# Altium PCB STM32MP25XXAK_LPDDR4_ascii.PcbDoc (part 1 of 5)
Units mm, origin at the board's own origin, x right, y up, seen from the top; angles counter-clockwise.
Board outline 120 x 79.6 mm, 4 copper layers (Top Layer, Signal Layer 1, Signal Layer 2, Bottom Layer), stack 1.614 mm thick; 190 components, 143 nets, 1208 pads, 757 vias.
Unrouted connection lines stored in the file: 3.
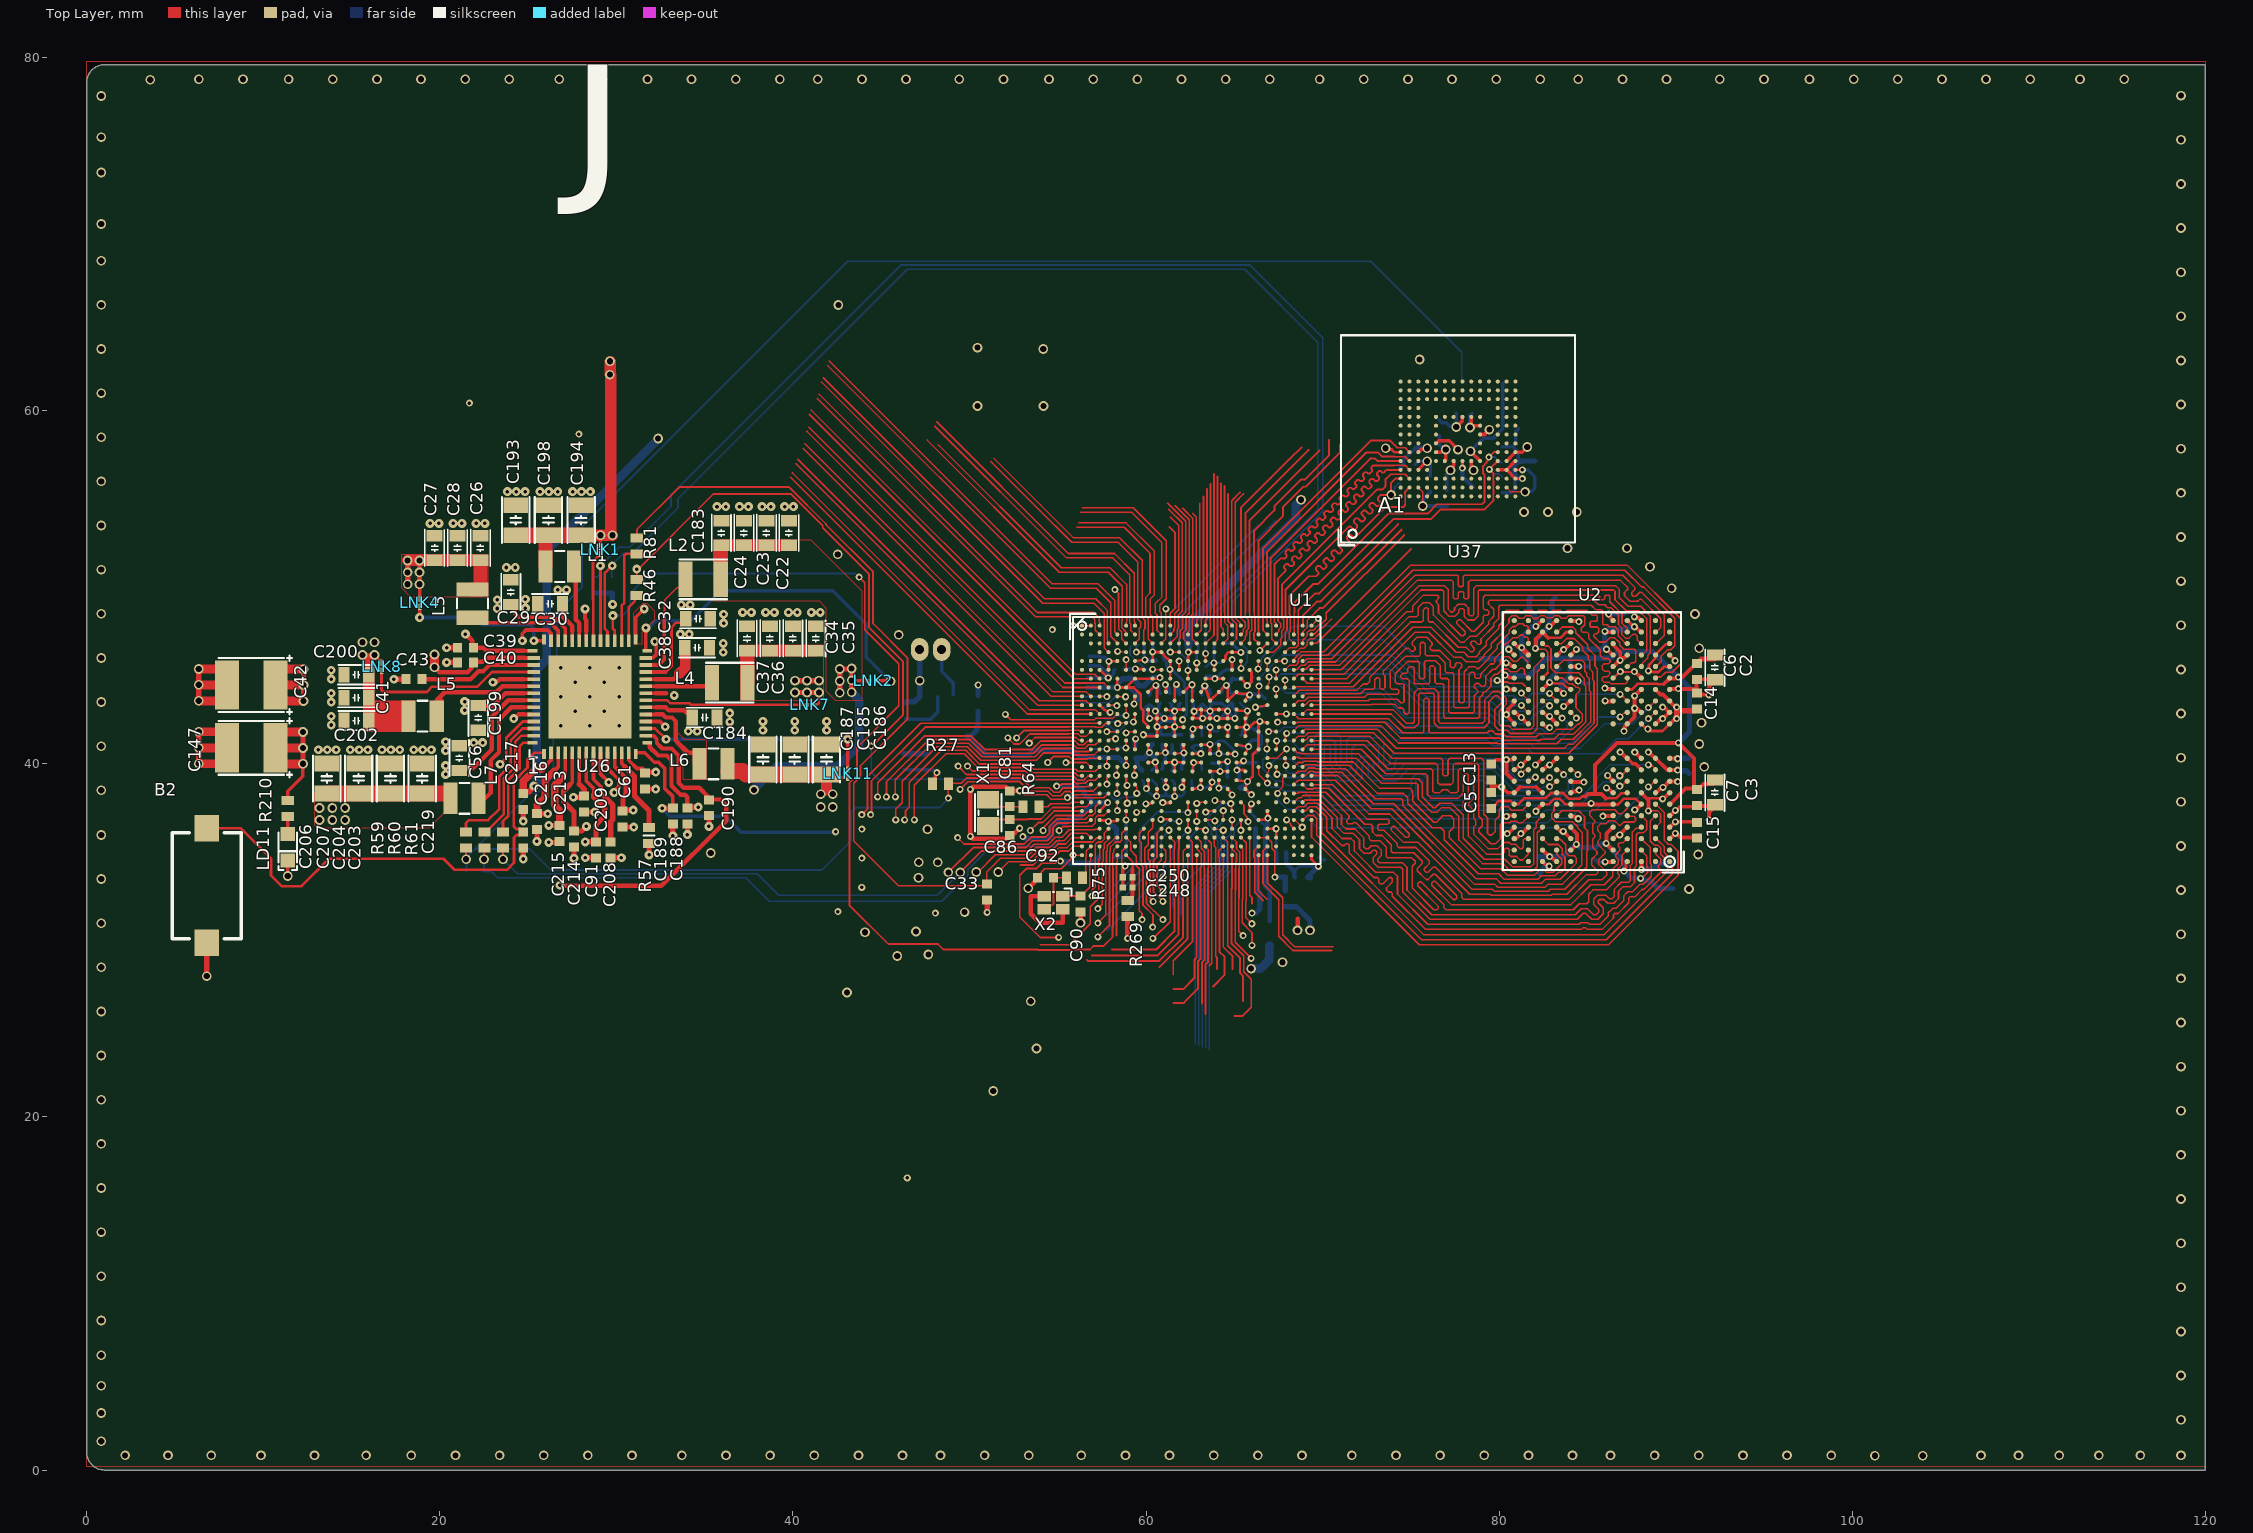
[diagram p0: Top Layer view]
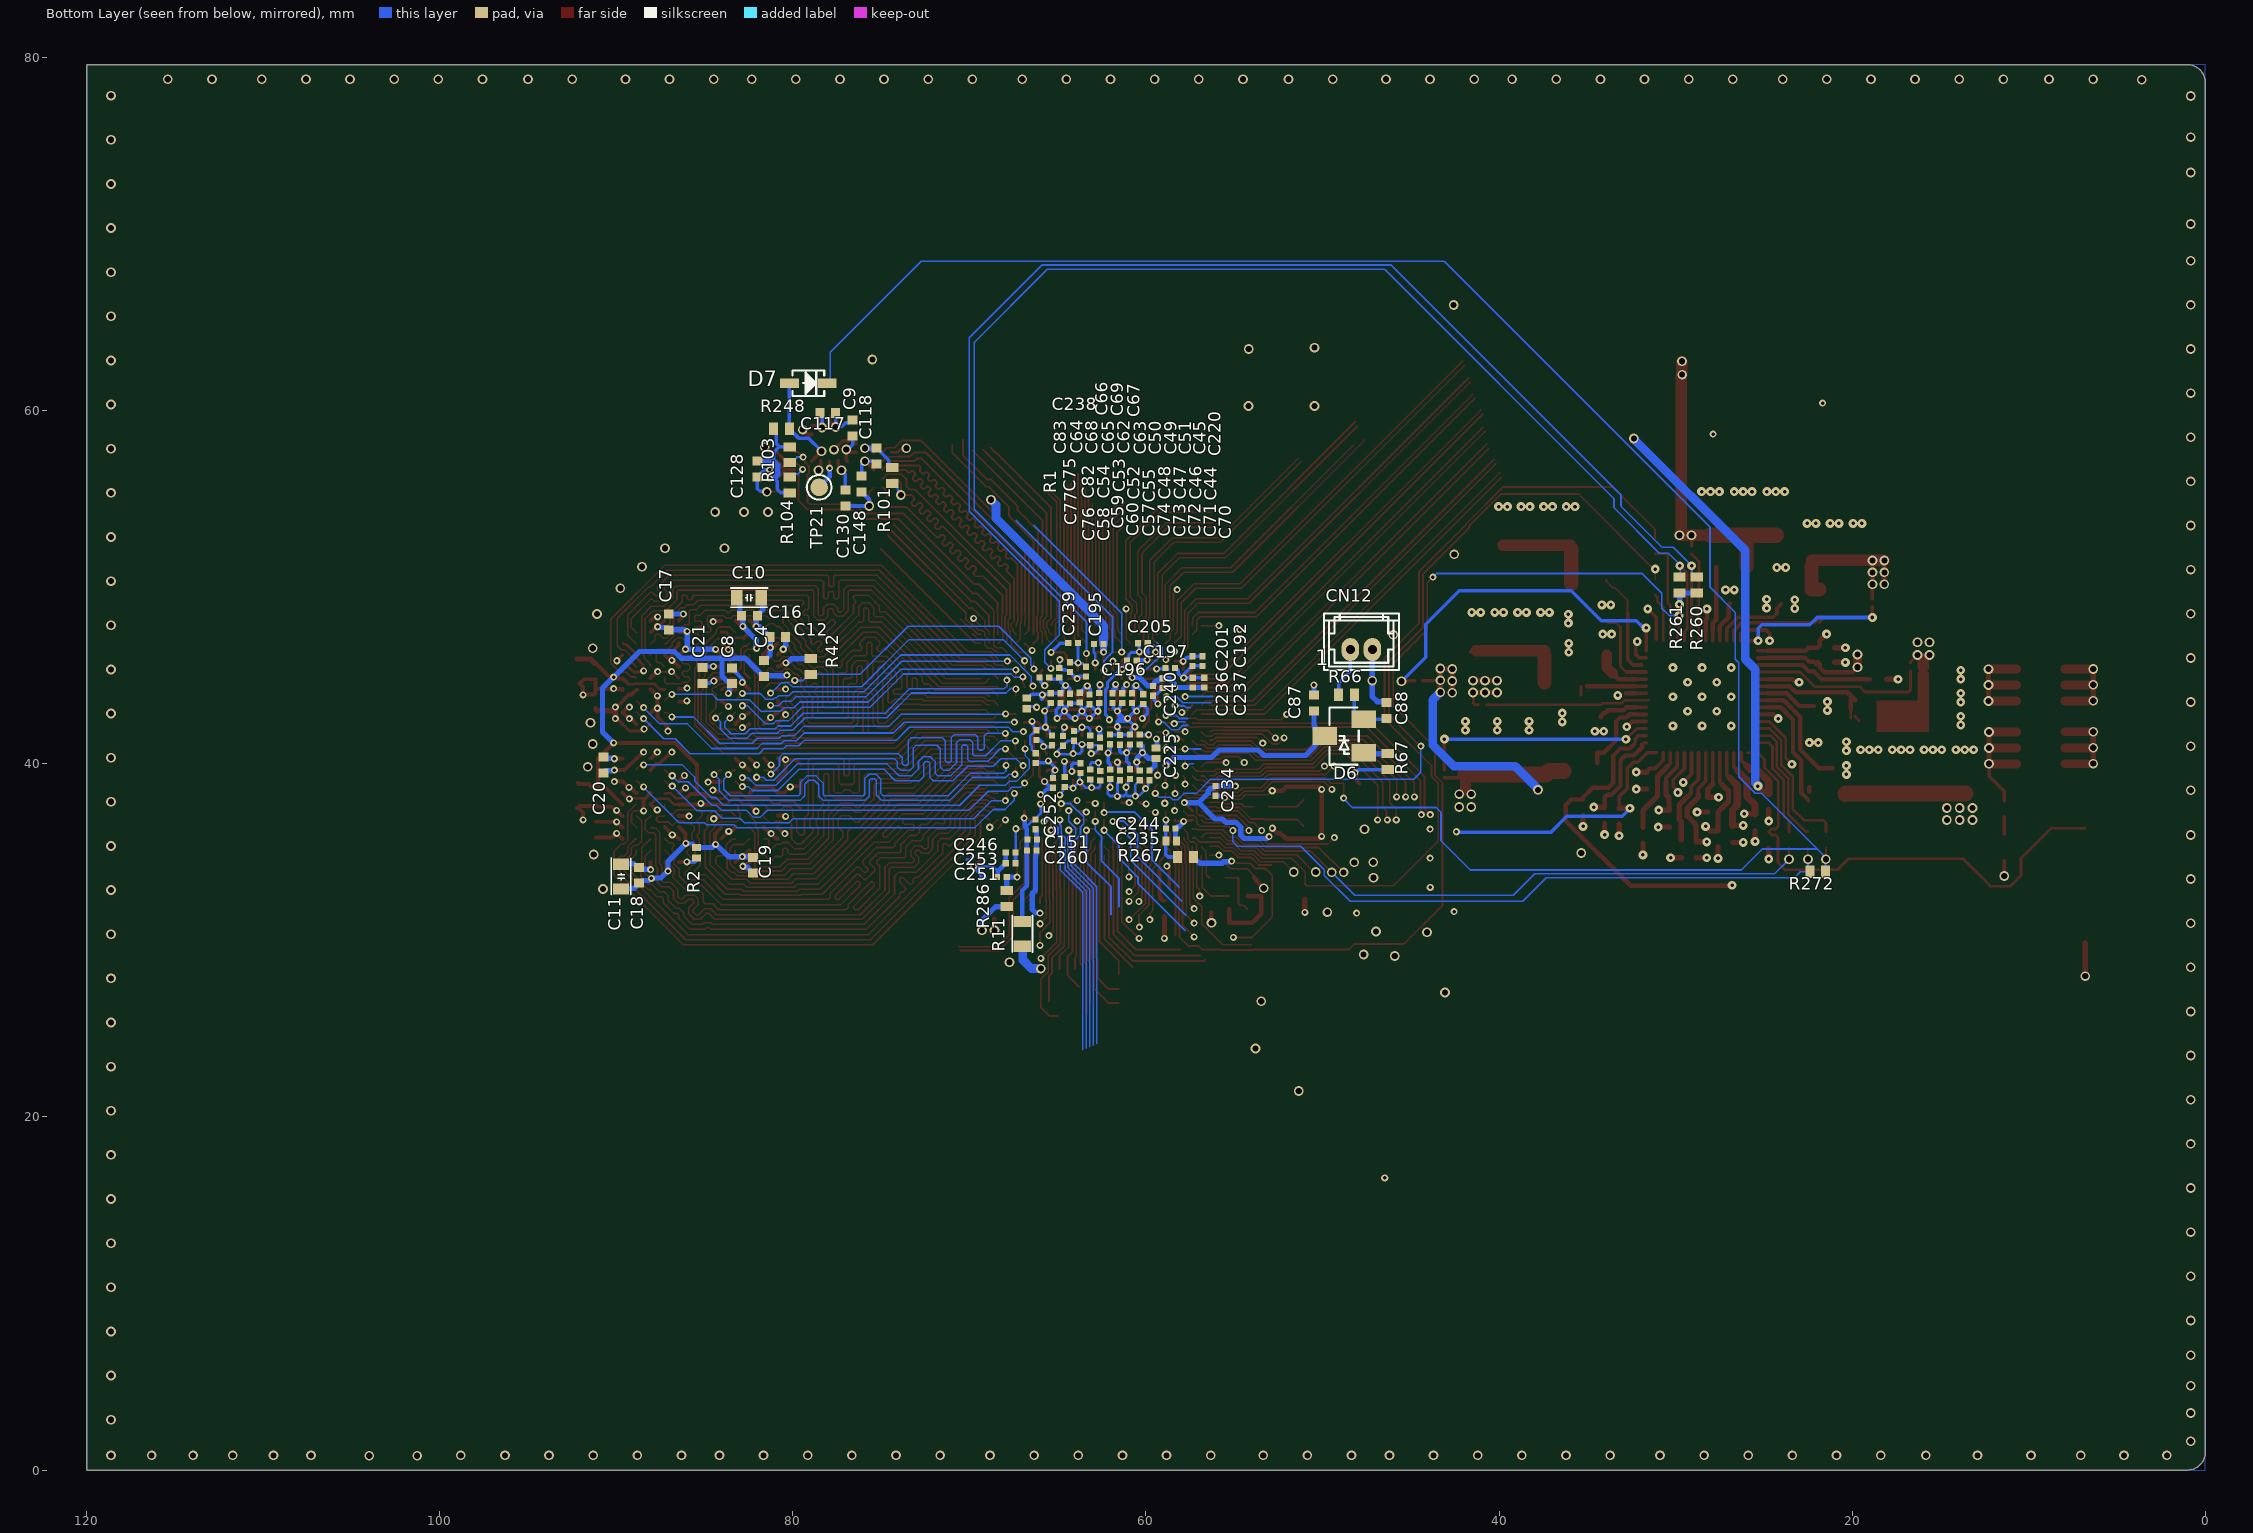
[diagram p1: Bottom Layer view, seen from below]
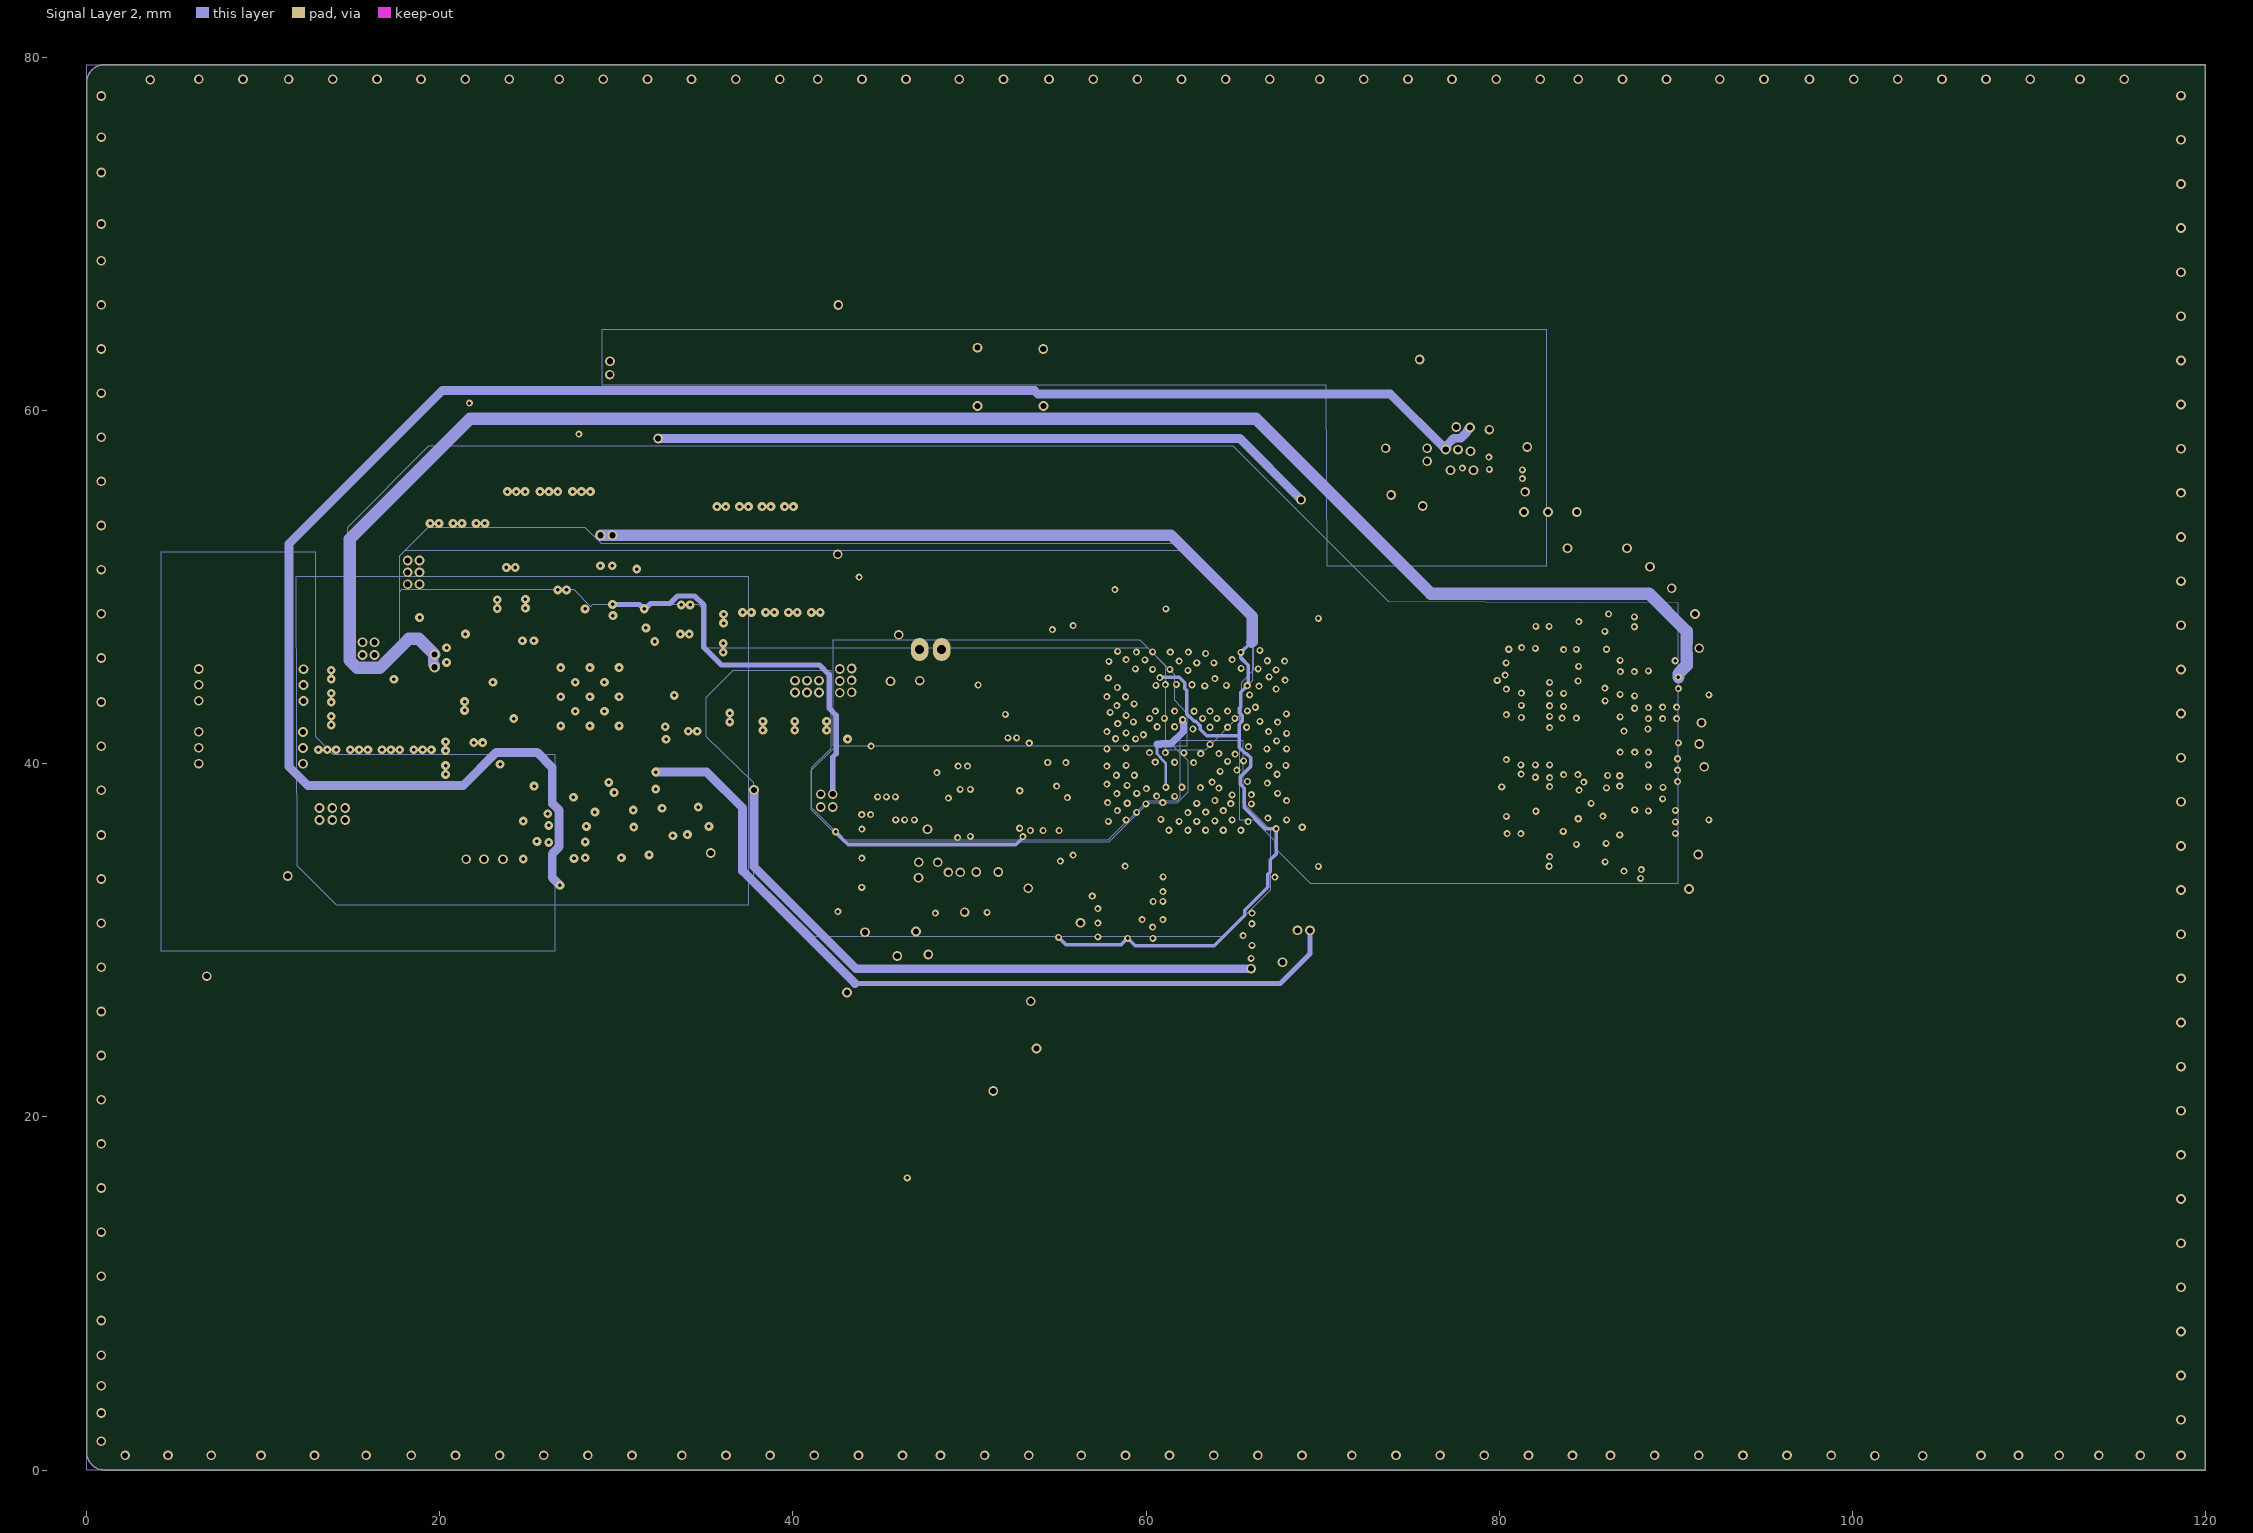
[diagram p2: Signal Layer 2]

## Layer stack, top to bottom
Top Solder: solder mask 0.025, Solder Resist, Dk 3.5
Top Layer: signal copper 0.037
Dielectric 1: prepreg 0.07, Dk 3.8
Signal Layer 1: signal copper 0.035
Dielectric 2: core 1.33, Dk 4.3
Signal Layer 2: signal copper 0.035
Dielectric 3: prepreg 0.07, Dk 3.8
Bottom Layer: signal copper 0.037
Bottom Solder: solder mask 0.025, Solder Resist, Dk 3.5

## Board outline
0,1 0,78.6 cw(c1,78.6) 1,79.6 120,79.6 120,0 1,0 cw(c1,1)

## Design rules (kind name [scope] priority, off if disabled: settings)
AssemblyTestPointUsage [All] p0: scope1count=1 scope1_0_kind=Board scope1_0_value=Board scope2count=1 scope2_0_kind=Board scope2_0_value=Board commentlength=0
AssemblyTestpoint [All] p0: scope1count=1 scope1_0_kind=Board scope1_0_value=Board scope2count=1 scope2_0_kind=Board scope2_0_value=Board commentlength=0
BoardOutlineClearance [All] p0: scope1count=1 scope1_0_kind=Board scope1_0_value=Board scope2count=1 scope2_0_kind=Board scope2_0_value=Board commentlength=0 gap=0.5
BoardOutlineClearance Silkscreen [All] p0 off: scope1count=1 scope1_0_kind=Board scope1_0_value=Board scope2count=1 scope2_0_kind=Board scope2_0_value=Board commentlength=90 gap=0 // Protel DXP Scope 1 Expression Was: OnLayer('Top Overlay') or OnLayer('Bottom Overlay')
BoardOutlineClearance Silkscreen [OnLayer('Top Overlay') or OnLayer('Bottom Overlay')] p1: gap=0 ignorepadtopadclearanceinfootprint=FALSE
BoardOutlineClearance [All] p2: gap=0.5 ignorepadtopadclearanceinfootprint=FALSE
Clearance Clearance_Default [All] p0: scope1count=1 scope1_0_kind=Board scope1_0_value=Board scope2count=1 scope2_0_kind=Board scope2_0_value=Board commentlength=0 gap=0.1
Clearance Clearance_Default [All] p1: gap=0.1 ignorepadtopadclearanceinfootprint=TRUE except(0: SMDPad-Hole Via-Hole; 0.09: Track-Track Track-SMDPad; 0.2: Arc-Hole Track-Hole THPad-Hole Fill-Hole Poly-Hole Region-Hole Text-Hole)
ComponentClearance [All] p0: scope1count=1 scope1_0_kind=Board scope1_0_value=Board scope2count=1 scope2_0_kind=Board scope2_0_value=Board commentlength=0 gap=0.2 collisioncheckmode=3
ComponentClearance [All] p1: gap=0.2 collisioncheckmode=3 verticalgap=0 showdistances=FALSE
DiffPairsRouting 100H [All] p0 off: scope1count=1 scope1_0_kind=Board scope1_0_value=Board scope2count=1 scope2_0_kind=Board scope2_0_value=Board commentlength=70 // Protel DXP Scope 1 Expression Was: InDifferentialPairClass('100H')
DiffPairsRouting 100H [InDifferentialPairClass('100H')] p1: maxlimit=0.254 minlimit=0.16 mostfreqgap=0.16 toplayer_maxgap=0.16 toplayer_minwidth=0.09 toplayer_maxwidth=0.09 toplayer_prefwidth=0.09 midlayer1_minwidth=0.09 midlayer1_maxwidth=0.381 midlayer1_prefwidth=0.09 midlayer4_minwidth=0.09 midlayer4_maxwidth=0.381 midlayer4_prefwidth=0.09 bottomlayer_maxgap=0.16 bottomlayer_minwidth=0.09 bottomlayer_maxwidth=0.09 bottomlayer_prefwidth=0.09 impedanceprofiledriven=TRUE impedanceprofileid={628B3294-B84C-4222-8D8D-B3EA8745C43E} impedanceprofilevalue=100.000000 maxuncoupledlength=12.7
FabricationTestPointUsage [All] p0: scope1count=1 scope1_0_kind=Board scope1_0_value=Board scope2count=1 scope2_0_kind=Board scope2_0_value=Board commentlength=0 valid=0 allowmultiple=FALSE
FabricationTestpoint [All] p0: scope1count=1 scope1_0_kind=Board scope1_0_value=Board scope2count=1 scope2_0_kind=Board scope2_0_value=Board commentlength=0 side=3 testpointundercomponent=TRUE minsize=1.016 maxsize=2.54 preferedsize=1.524 minholesize=0 maxholesize=1.016 preferedholesize=0.813 testpointgrid=0.025
FanoutControl Fanout_Default [All] p0: scope1count=1 scope1_0_kind=Board scope1_0_value=Board scope2count=1 scope2_0_kind=Board scope2_0_value=Board commentlength=30 // Fanout_Default (Default Rule)
FanoutControl Fanout_Small [All] p0 off: scope1count=1 scope1_0_kind=Board scope1_0_value=Board scope2count=1 scope2_0_kind=Board scope2_0_value=Board commentlength=84 // Protel DXP Scope 1 Expression Was: (CompPinCount < 5)   Fanout_Small (Default Rule)
FanoutControl Fanout_SOIC [All] p0 off: scope1count=1 scope1_0_kind=Board scope1_0_value=Board scope2count=1 scope2_0_kind=Board scope2_0_value=Board commentlength=71 // Protel DXP Scope 1 Expression Was: IsSOIC   Fanout_SOIC (Default Rule)
FanoutControl Fanout_LCC [All] p0 off: scope1count=1 scope1_0_kind=Board scope1_0_value=Board scope2count=1 scope2_0_kind=Board scope2_0_value=Board commentlength=69 // Protel DXP Scope 1 Expression Was: IsLCC   Fanout_LCC (Default Rule)
FanoutControl Fanout_BGA [All] p0 off: scope1count=1 scope1_0_kind=Board scope1_0_value=Board scope2count=1 scope2_0_kind=Board scope2_0_value=Board commentlength=69 // Protel DXP Scope 1 Expression Was: IsBGA   Fanout_BGA (Default Rule)
FanoutControl Fanout_BGA [IsBGA] p1: bgadir=Out bgaviamode=Closest fanoutstyle=Auto fanoutdirection=Alternating viagrid=0.025 // Fanout_BGA (Default Rule)
FanoutControl Fanout_LCC [IsLCC] p2: bgadir=Out bgaviamode=Closest fanoutstyle=Auto fanoutdirection=Alternating viagrid=0.025 // Fanout_LCC (Default Rule)
FanoutControl Fanout_SOIC [IsSOIC] p3: bgadir=Out bgaviamode=Closest fanoutstyle=Auto fanoutdirection=Alternating viagrid=0.025 // Fanout_SOIC (Default Rule)
FanoutControl Fanout_Small [(CompPinCount < 5)] p4: bgadir=Out bgaviamode=Closest fanoutstyle=Auto fanoutdirection=OutThenIn viagrid=0.025 // Fanout_Small (Default Rule)
FanoutControl Fanout_Default [All] p5: bgadir=Out bgaviamode=Closest fanoutstyle=Auto fanoutdirection=Alternating viagrid=0.025 // Fanout_Default (Default Rule)
Height [All] p0: scope1count=1 scope1_0_kind=Board scope1_0_value=Board scope2count=1 scope2_0_kind=Board scope2_0_value=Board commentlength=0
HoleSize [All] p0: scope1count=1 scope1_0_kind=Board scope1_0_value=Board scope2count=1 scope2_0_kind=Board scope2_0_value=Board commentlength=0 absolutevalues=TRUE maxlimit=10 minlimit=0.1 maxpercent=80.000 minpercent=20.000
HoleSize [All] p1: absolutevalues=TRUE maxlimit=10 minlimit=0.1 maxpercent=80.000 minpercent=20.000
HoleToHoleClearance [All] p0: scope1count=1 scope1_0_kind=Board scope1_0_value=Board scope2count=1 scope2_0_kind=Board scope2_0_value=Board commentlength=0
HoleToHoleClearance [All] p1: gap=0.25 allowstackedmicrovias=TRUE
LayerPairs [All] p0: scope1count=1 scope1_0_kind=Board scope1_0_value=Board scope2count=1 scope2_0_kind=Board scope2_0_value=Board commentlength=0 enforce=TRUE
MinimumSolderMaskSliver MinimumSolderMaskSliver_SOLDER_BRIDGE [All] p0: scope1count=1 scope1_0_kind=Board scope1_0_value=Board scope2count=1 scope2_0_kind=Footprint scope2_0_value=SOLDER-BRIDGE_R0603-0R commentlength=0
MinimumSolderMaskSliver [All] p0: scope1count=1 scope1_0_kind=Board scope1_0_value=Board scope2count=1 scope2_0_kind=Board scope2_0_value=Board commentlength=0
MinimumSolderMaskSliver MinimumSolderMaskSliver_SOLDER_BRIDGE [All vs HasFootprint('SOLDER-BRIDGE_R0603-0R')] p1: minsoldermaskwidth=0.07
MinimumSolderMaskSliver [All] p2: minsoldermaskwidth=0.075
NetAntennae [All] p0 off: scope1count=1 scope1_0_kind=Board scope1_0_value=Board scope2count=1 scope2_0_kind=Board scope2_0_value=Board commentlength=0
NetAntennae [All] p1 off: netantennaetolerance=0
PasteMaskExpansion [All] p0: scope1count=1 scope1_0_kind=Board scope1_0_value=Board scope2count=1 scope2_0_kind=Board scope2_0_value=Board commentlength=0 expansion=0
PlaneClearance [All] p0: scope1count=1 scope1_0_kind=Board scope1_0_value=Board scope2count=1 scope2_0_kind=Board scope2_0_value=Board commentlength=0 clearance=0.508
PlaneConnect [All] p0: scope1count=1 scope1_0_kind=Board scope1_0_value=Board scope2count=1 scope2_0_kind=Board scope2_0_value=Board commentlength=0 planeconnectstyle=Direct reliefexpansion=0.508 reliefentries=4 reliefconductorwidth=0.21 reliefairgap=0.21
PlaneConnect [All] p1: planeconnectstyle=Direct reliefexpansion=0.508 reliefentries=4 reliefconductorwidth=0.21 reliefairgap=0.21
PolygonConnect PolygonConnect_Default [All] p0: scope1count=1 scope1_0_kind=Board scope1_0_value=Board scope2count=1 scope2_0_kind=Board scope2_0_value=Board commentlength=0 connectstyle=Direct reliefconductorwidth=0.25 reliefentries=4 polygonreliefangle="90 Angle"
PolygonConnect PolygonConnect_Default [All] p1: connectstyle=Direct reliefconductorwidth=0.25 reliefentries=4 polygonreliefangle="90 Angle" airgapwidth=0.25
RoomDefinition RoomDefinition_eMMC [All] p0 off: scope1count=1 scope1_0_kind=Board scope1_0_value=Board scope2count=1 scope2_0_kind=Board scope2_0_value=Board commentlength=44 region_x1=366825123 region_y1=339606300 region_x2=369695387 region_y2=342521149 confinementstyle=ConfineIn // Protel DXP Scope 1 Expression Was: False
RoomDefinition RoomDefinition_DDR [All] p0 off: scope1count=1 scope1_0_kind=Board scope1_0_value=Board scope2count=1 scope2_0_kind=Board scope2_0_value=Board commentlength=44 region_x1=368782677 region_y1=331242320 region_x2=373417322 region_y2=337462792 confinementstyle=ConfineIn // Protel DXP Scope 1 Expression Was: False
RoomDefinition U_PMIC [All] p0: scope1count=1 scope1_0_kind=ComponentClass scope1_0_value=U_PMIC scope2count=1 scope2_0_kind=Board scope2_0_value=Board commentlength=0 region_x1=359568897 region_y1=331484252 region_x2=365277559 region_y2=337192914 confinementstyle=ConfineIn
RoomDefinition RoomDefinition_eMMC [False] p1: confinementstyle=ConfineIn formatcopy=TRUE lockcomponents=FALSE outline 74.056,62.109 81.346,62.109 81.346,54.705 74.056,54.705
RoomDefinition RoomDefinition_DDR [False] p2: confinementstyle=ConfineIn formatcopy=TRUE lockcomponents=FALSE outline 79.028,49.26 90.8,49.26 90.8,33.46 79.028,33.46
RoomDefinition U_PMIC [InComponentClass('U_PMIC')] p3: confinementstyle=ConfineIn formatcopy=TRUE lockcomponents=FALSE outline 55.625,48.575 70.125,48.575 70.125,34.075 55.625,34.075
RoutingCorners [All] p0: scope1count=1 scope1_0_kind=Board scope1_0_value=Board scope2count=1 scope2_0_kind=Board scope2_0_value=Board commentlength=0 cornerstyle=45-Degree minsetback=2.54 maxsetback=2.54
RoutingLayers [All] p0: scope1count=1 scope1_0_kind=Board scope1_0_value=Board scope2count=1 scope2_0_kind=Board scope2_0_value=Board commentlength=0 top layer=Automatic mid layer 1=Automatic mid layer 4=Automatic bottom layer=Automatic
RoutingPriority [All] p0: scope1count=1 scope1_0_kind=Board scope1_0_value=Board scope2count=1 scope2_0_kind=Board scope2_0_value=Board commentlength=0
RoutingTopology [All] p0: scope1count=1 scope1_0_kind=Board scope1_0_value=Board scope2count=1 scope2_0_kind=Board scope2_0_value=Board commentlength=0 topology=Shortest
RoutingVias RoutingVias_Default [All] p0 off: scope1count=1 scope1_0_kind=Board scope1_0_value=Board scope2count=1 scope2_0_kind=Board scope2_0_value=Board commentlength=83 holewidth=0.15 width=0.4 viastyle="Through Hole" minholewidth=0.15 minwidth=0.4 maxholewidth=0.35 maxwidth=0.6 // Protel DXP Scope 1 Expression Was: InDrillLayerPair('Top Layer - Bottom Layer')
RoutingVias RoutingVias_Default [InDrillLayerPair('Top Layer - Bottom Layer')] p1: holewidth=0.15 width=0.4 viastyle="Through Hole" minholewidth=0.15 minwidth=0.4 maxholewidth=0.35 maxwidth=0.6 useviatemplates=TRUE viatemplateguid#1={8082EAB8-D593-4669-9C8E-234CD125C595} viatemplateguid#2={6F43EA8F-9356-47F3-9E64-8437B01C3073} viatemplateguid#3={0C56A9B8-CF93-463B-97D5-BDCC265789B0} viatemplateguid#4={9F28DA9E-6088-4B56-A5CF-E6C86A3E97F7} viatemplatename#1=v40h20m0mx0 viatemplatename#2=v40h20m25 viatemplatename#3=v50h20m25 viatemplatename#4=v55h35m40mx40
ShortCircuit [All] p0: scope1count=1 scope1_0_kind=Board scope1_0_value=Board scope2count=1 scope2_0_kind=Board scope2_0_value=Board commentlength=0 allowed=FALSE
SilkToBoardRegionClearance [All] p0: scope1count=1 scope1_0_kind=Board scope1_0_value=Board scope2count=1 scope2_0_kind=Board scope2_0_value=Board commentlength=0
SilkToSilkClearance [All] p0: scope1count=1 scope1_0_kind=Board scope1_0_value=Board scope2count=1 scope2_0_kind=Board scope2_0_value=Board commentlength=0
SilkToSilkClearance [All] p1: silktosilkclearance=0.2
SilkToSolderMaskClearance [All] p0 off: scope1count=1 scope1_0_kind=Board scope1_0_value=Board scope2count=1 scope2_0_kind=Board scope2_0_value=Board commentlength=44 // Protel DXP Scope 1 Expression Was: IsPad
SilkToSolderMaskClearance [IsPad] p1: minsilkscreentomaskgap=0.015 clearancetoexposedcopper=TRUE
SolderMaskExpansion [All] p0: scope1count=1 scope1_0_kind=Board scope1_0_value=Board scope2count=1 scope2_0_kind=Board scope2_0_value=Board commentlength=0 expansion=0.1
SolderMaskExpansion [All] p1: expansion=0.1 istentingtop=FALSE
UnRoutedNet [All] p0 off: scope1count=1 scope1_0_kind=Board scope1_0_value=Board scope2count=1 scope2_0_kind=Board scope2_0_value=Board commentlength=0
UnRoutedNet [All] p1 off:
UnpouredPolygon [All] p0: scope1count=1 scope1_0_kind=Board scope1_0_value=Board scope2count=1 scope2_0_kind=Board scope2_0_value=Board commentlength=0
ViasUnderSMD [All] p0: scope1count=1 scope1_0_kind=PadClass scope1_0_value=PC_VIAS-IN-PAD_OK scope2count=1 scope2_0_kind=Board scope2_0_value=Board commentlength=0 allowed=TRUE
ViasUnderSMD [InPadClass('PC_VIAS-IN-PAD_OK')] p1: allowed=TRUE
Width Width_Default [All] p0: scope1count=1 scope1_0_kind=Net scope1_0_value=GND scope2count=1 scope2_0_kind=Board scope2_0_value=Board commentlength=0 maxlimit=10 minlimit=0.09 preferedwidth=0.3
Width Width_SINGLE_DDR_55R [All] p0 off: scope1count=1 scope1_0_kind=NetClass scope1_0_value=55H scope2count=1 scope2_0_kind=Board scope2_0_value=Board commentlength=0 maxlimit=0.199 minlimit=0.078 preferedwidth=0.199
Width Width_SINGLE_50R [All] p0 off: scope1count=1 scope1_0_kind=NetClass scope1_0_value=50H scope2count=1 scope2_0_kind=Board scope2_0_value=Board commentlength=0 maxlimit=0.199 minlimit=0.078 preferedwidth=0.199
Width Width_SINGLE_50R [InNetClass('50H')] p1 off: maxlimit=0.199 minlimit=0.078 preferedwidth=0.199 toplayer_minwidth=0.09 toplayer_maxwidth=0.11 toplayer_prefwidth=0.11 bottomlayer_minwidth=0.11 bottomlayer_maxwidth=0.11 bottomlayer_prefwidth=0.11 impedanceprofiledriven=TRUE impedanceprofileid={152E730A-FDA4-4006-BF82-0EE0D5C1A339} impedanceprofilevalue=50.000000 minimp=50.000000 maximp=50.000000 favimp=50.000000
Width Width_SINGLE_DDR_55R [InNetClass('55H')] p2 off: maxlimit=0.199 minlimit=0.078 preferedwidth=0.199 toplayer_minwidth=0.09 toplayer_maxwidth=0.09 toplayer_prefwidth=0.09 bottomlayer_minwidth=0.09 bottomlayer_maxwidth=0.09 bottomlayer_prefwidth=0.09 impedanceprofiledriven=TRUE impedanceprofileid={D5948A69-504E-4D29-B9E5-77B49DDD78E4} impedanceprofilevalue=55.000000 minimp=50.000000 maximp=50.000000 favimp=50.000000
Width Width_Default [InNet('GND')] p3: maxlimit=10 minlimit=0.09 preferedwidth=0.3 toplayer_prefwidth=0.09 bottomlayer_prefwidth=0.09 minimp=50.000000 maximp=50.000000 favimp=50.000000
15 further rules are at their usual default settings.

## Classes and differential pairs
net class 100H: DDR_CLK_A_N DDR_CLK_A_P DDR_CLK_B_N DDR_CLK_B_P DDR_DQS0_A_N DDR_DQS0_A_P DDR_DQS0_B_N DDR_DQS0_B_P DDR_DQS1_A_N DDR_DQS1_A_P DDR_DQS1_B_N DDR_DQS1_B_P
net class eMMC.SDMMC2_D[0..7]: eMMC.SDMMC2_CK eMMC.SDMMC2_CMD eMMC.SDMMC2_D0 eMMC.SDMMC2_D1 eMMC.SDMMC2_D2 eMMC.SDMMC2_D3 eMMC.SDMMC2_D4 eMMC.SDMMC2_D5 eMMC.SDMMC2_D6 eMMC.SDMMC2_D7
component class U_eMMC: C9 C117 C118 C128 C130 C148 D7 R101 R103 R104 R248 TP21 U37
component class "U_STM32MP25XXAK I_Os": C33 C81 C86 C90 C92 R27 R64 R75 R260 R261 R272 U1 X1 X2
component class "U_STM32MP25XXAK Power": C44 C45 C46 C47 C48 C49 C50 C51 C52 C53 C54 C55 C57 C58 C59 C60 C62 C63 C64 C65 C66 C67 C68 C69 C70 C71 C72 C73 C74 C75 C76 C77 C82 C83 C87 C88 C151 C192 C195 C196 C197 C201 C205 C220 C225 C234 C235 C236 C237 C238 C239 C240 C244 C246 C248 C250 C251 C252 C253 C260 CN12 D6 R11 R66 R67 R267 R269 R286
component class U_PMIC: B2 C22 C23 C24 C26 C27 C28 C29 C30 C32 C34 C35 C36 C37 C38 C39 C40 C41 C42 C43 C56 C61 C91 C147 C183 C184 C185 C186 C187 C188 C189 C190 C193 C194 C198 C199 C200 C202 C203 C204 C206 C207 C208 C209 C213 C214 C215 C216 C217 C219 L1 L2 L3 L4 L5 L6 L7 LD11 LNK1 LNK2 LNK4 LNK7 LNK8 LNK11 R46 R57 R59 R60 R61 R81 R210 U26
differential pair CLKB: +DDR_CLK_B_P -DDR_CLK_B_N
differential pair CLKA: +DDR_CLK_A_P -DDR_CLK_A_N
differential pair DQS1B: +DDR_DQS1_B_P -DDR_DQS1_B_N
differential pair DQS0B: +DDR_DQS0_B_P -DDR_DQS0_B_N
differential pair DQS1A: +DDR_DQS1_A_P -DDR_DQS1_A_N
differential pair " ": +DDR_DQS0_A_P -DDR_DQS0_A_N

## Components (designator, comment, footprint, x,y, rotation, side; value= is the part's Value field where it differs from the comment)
B2 "SW_PUSH_SMD_2P" SWI_WE_434121025816 6.795,33.104 r90 top
C2 "Capacitor" C0603 92.225,45.46 r90 top
C3 "Capacitor" C0603 92.225,38.385 r90 top
C4 "100nF" C0402 81.63,45.397 r90 bottom
C5 "100nF" C0402 79.559,37.929 r90 top
C6 "100nF" C0402 91.209,45.24 r270 top
C7 "100nF" C0402 91.209,38.09 r270 top
C8 "100nF" C0402 83.461,44.99 r90 bottom
C9 "Capacitor" C0402 76.615,59.03 r270 bottom
C10 "Capacitor" C0603 82.486,49.415 r0 bottom
C11 "Capacitor" C0603 89.736,33.615 r270 bottom
C12 "100nF" C0402 80.861,47.18 r0 bottom
C13 "100nF" C0402 79.559,39.529 r270 top
C14 "100nF" C0402 91.209,43.565 r90 top
C15 "100nF" C0402 91.209,36.24 r270 top
C16 "100nF" C0402 82.461,48.39 r180 bottom
C17 "100nF" C0402 87.036,48.04 r90 bottom
C18 "100nF" C0402 88.711,33.69 r90 bottom
C19 "100nF" C0402 82.261,34.255 r270 bottom
C20 "100nF" C0402 90.736,39.94 r270 bottom
C21 "100nF" C0402 85.111,45.015 r90 bottom
C22 "Capacitor" C0603 39.775,53.075 r270 top
C23 "Capacitor" C0603 38.5,53.075 r270 top
C24 "Capacitor" C0603 37.225,53.075 r270 top
C26 "Capacitor" C0603 22.3,52.225 r270 top
C27 "Capacitor" C0603 19.7,52.225 r270 top
C28 "Capacitor" C0603 21,52.225 r270 top
C29 "Capacitor" C0603 24.025,49.725 r270 top
C30 "Capacitor" C0603 26.25,49.075 r0 top
C32 "Capacitor" C0603 34.625,48.225 r180 top
C33 "Capacitor" C0402 51,32.75 r90 top
C34 "Capacitor" C0603 40,47.1 r270 top
C35 "Capacitor" C0603 41.3,47.1 r270 top
C36 "Capacitor" C0603 38.7,47.1 r270 top
C37 "Capacitor" C0603 37.4,47.1 r270 top
C38 "Capacitor" C0603 34.575,46.575 r180 top
C39 "Capacitor" C0402 21.445,46.575 r0 top
C40 "Capacitor" C0402 21.445,45.75 r0 top
C41 "Capacitor" C0603 15.275,43.75 r0 top
C42 "Cap_POL_TANA" CPOL_TCJ-B_1210_H210 9.311,44.468 r180 top
C43 "Capacitor" C0402 18.535,44.8 r0 top
C44 "1uF" C0201_MURATA_GRM033_H0P3 60.351,41.38 r270 bottom
C45 "1uF" C0201_MURATA_GRM033_H0P3 60.16,43.67 r270 bottom
C46 "1uF" C0201_MURATA_GRM033_H0P3 60.915,41.38 r90 bottom
C47 "1uF" C0201_MURATA_GRM033_H0P3 61.476,41.356 r270 bottom
C48 "1uF" C0201_MURATA_GRM033_H0P3 62.038,41.382 r90 bottom
C49 "1uF" C0201_MURATA_GRM033_H0P3 61.35,43.725 r270 bottom
C50 "1uF" C0201_MURATA_GRM033_H0P3 61.9,43.725 r270 bottom
C51 "1uF" C0201_MURATA_GRM033_H0P3 60.8,43.725 r270 bottom
C52 "1uF" C0201_MURATA_GRM033_H0P3 63.162,41.332 r270 bottom
C53 "1uF" C0201_MURATA_GRM033_H0P3 64.083,41.581 r270 bottom
C54 "1uF" C0201_MURATA_GRM033_H0P3 64.706,41.304 r270 bottom
C55 "1uF" C0201_MURATA_GRM033_H0P3 62.6,41.2 r270 bottom
C56 "Capacitor" C0603 21.1,40.325 r270 top
C57 "1uF" C0201_MURATA_GRM033_H0P3 62.592,39.328 r270 bottom
C58 "1uF" C0201_MURATA_GRM033_H0P3 64.607,38.972 r270 bottom
C59 "1uF" C0201_MURATA_GRM033_H0P3 63.714,39.761 r270 bottom
C60 "1uF" C0201_MURATA_GRM033_H0P3 63.154,39.397 r270 bottom
C61 "Capacitor" C0402 31.625,39.02 r90 top
C62 "1uF" C0201_MURATA_GRM033_H0P3 63.2,43.65 r90 bottom
C63 "1uF" C0201_MURATA_GRM033_H0P3 62.65,43.73 r270 bottom
C64 "1uF" C0201_MURATA_GRM033_H0P3 64.85,43.725 r270 bottom
C65 "1uF" C0201_MURATA_GRM033_H0P3 63.75,43.75 r90 bottom
C66 "1uF" C0201_MURATA_GRM033_H0P3 64.915,45.16 r90 bottom
C67 "1uF" C0201_MURATA_GRM033_H0P3 63.4,45.225 r270 bottom
C68 "1uF" C0201_MURATA_GRM033_H0P3 64.3,43.7 r270 bottom
C69 "1uF" C0201_MURATA_GRM033_H0P3 64.305,45.477 r270 bottom
C70 "1uF" C0201_MURATA_GRM033_H0P3 59.805,39.35 r90 bottom
C71 "1uF" C0201_MURATA_GRM033_H0P3 60.355,39.35 r270 bottom
C72 "1uF" C0201_MURATA_GRM033_H0P3 60.905,39.423 r270 bottom
C73 "1uF" C0201_MURATA_GRM033_H0P3 61.467,39.349 r90 bottom
C74 "1uF" C0201_MURATA_GRM033_H0P3 62.03,39.408 r270 bottom
C75 "1uF" C0201_MURATA_GRM033_H0P3 66.205,41.625 r90 bottom
C76 "1uF" C0201_MURATA_GRM033_H0P3 65.274,38.923 r270 bottom
C77 "1uF" C0201_MURATA_GRM033_H0P3 66.25,40.325 r270 bottom
C81 "Capacitor" C0402 52.285,38.025 r90 top
C82 "1uF" C0201_MURATA_GRM033_H0P3 65.325,41.325 r90 bottom
C83 "1uF" C0201_MURATA_GRM033_H0P3 65.395,43.725 r270 bottom
C86 "Capacitor" C0402 52.285,36.4 r270 top
C87 "" C0402 50.485,43.438 r270 bottom
C88 "Capacitor" C0402 46.382,43.015 r270 bottom
C90 "Capacitor" C0402 56.293,32.06 r90 top
C91 "Capacitor" C0402 28.85,35.13 r270 top
C92 "Capacitor" C0402 54.309,33.546 r180 top
C117 "Capacitor" C0402 78.025,59.864 r0 bottom
C118 "Capacitor" C0402 75.26,57.43 r90 bottom
C128 "Capacitor" C0402 82.015,56.705 r90 bottom
C130 "Capacitor" C0402 77.027,55.055 r270 bottom
C147 "Cap_POL_TANA" CPOL_TCJ-B_1210_H210 9.311,40.906 r180 top
C148 "Capacitor" C0402 76.11,55.855 r270 bottom
C151 "Capacitor" C0201_MURATA_GRM033_H0P3 66.446,35.716 r0 bottom
C183 "Capacitor" C0603 35.95,53.075 r270 top
C184 "Capacitor" C0603 34.997,42.625 r180 top
C185 "Capacitor" C0805 40.1,40.25 r270 top
C186 "Capacitor" C0805 41.9,40.25 r270 top
C187 "Capacitor" C0805 38.3,40.25 r270 top
C188 "Capacitor" C0402 34.025,37.04 r90 top
C189 "Capacitor" C0402 33.2,37.04 r90 top
C190 "Capacitor" C0402 35.25,37.515 r270 top
C192 "Capacitor" C0201_MURATA_GRM033_H0P3 56.8,45.825 r90 bottom
C193 "Capacitor" C0805 24.3,53.8 r270 top
C194 "Capacitor" C0805 28,53.8 r270 top
C195 "Capacitor" C0201_MURATA_GRM033_H0P3 62.675,46.787 r180 bottom
C196 "Capacitor" C0201_MURATA_GRM033_H0P3 60.8,45.85 r0 bottom
C197 "Capacitor" C0201_MURATA_GRM033_H0P3 58.625,45.425 r0 bottom
C198 "Capacitor" C0805 26.15,53.8 r270 top
C199 "Capacitor" C0603 22.175,42.6 r90 top
C200 "Capacitor" C0603 15.275,45.05 r0 top
C201 "Capacitor" C0201_MURATA_GRM033_H0P3 57.375,45.825 r90 bottom
C202 "Capacitor" C0603 15.275,42.45 r0 top
C203 "Capacitor" C0805 19,39.173 r270 top
C204 "Capacitor" C0805 17.2,39.173 r270 top
C205 "Capacitor" C0201_MURATA_GRM033_H0P3 60.177,46.829 r0 bottom
C206 "Capacitor" C0805 13.6,39.173 r270 top
C207 "Capacitor" C0805 15.4,39.173 r270 top
C208 "Capacitor" C0402 29.675,35.13 r270 top
C209 "Capacitor" C0402 30.35,36.87 r90 top
C213 "Capacitor" C0402 28.175,37.72 r90 top
C214 "Capacitor" C0402 27.6,35.75 r270 top
C215 "Capacitor" C0402 26.775,36.06 r270 top
C216 "Capacitor" C0402 25.5,36.725 r90 top
C217 "Capacitor" C0402 24.725,37.87 r270 top
C219 "Capacitor" C0402 24.727,35.695 r90 top
C220 "Capacitor" C0201_MURATA_GRM033_H0P3 59.609,44.131 r90 bottom
C225 "Capacitor" C0201_H0P5 59.425,40.6 r90 bottom
C234 "Capacitor" C0201_MURATA_GRM033_H0P3 56.064,38.473 r90 bottom
C235 "Capacitor" C0201_H0P5 58.575,35.625 r0 bottom
C236 "Capacitor" C0201_MURATA_GRM033_H0P3 57.35,44.6 r270 bottom
C237 "Capacitor" C0201_MURATA_GRM033_H0P3 56.696,44.605 r270 bottom
C238 "Capacitor" C0201_MURATA_GRM033_H0P3 65.758,44.894 r0 bottom
C239 "Capacitor" C0201_MURATA_GRM033_H0P3 64.125,46.837 r0 bottom
C240 "Capacitor" C0201_MURATA_GRM033_H0P3 59.05,44.575 r90 bottom
C244 "Capacitor" C0201_MURATA_GRM033_H0P3 58.6,36.331 r0 bottom
C246 "Capacitor" C0201_MURATA_GRM033_H0P3 67.666,34.986 r180 bottom
C248 "Capacitor" C0201_MURATA_GRM033_H0P3 58.958,33.002 r0 top
C250 "Capacitor" C0201_MURATA_GRM033_H0P3 58.958,33.572 r0 top
C251 "Capacitor" C0201_MURATA_GRM033_H0P3 68.165,33.588 r180 bottom
C252 "Capacitor" C0201_MURATA_GRM033_H0P3 66.255,36.575 r90 bottom
C253 "Capacitor" C0201_MURATA_GRM033_H0P3 67.666,34.367 r180 bottom
C260 "Capacitor" C0201_MURATA_GRM033_H0P3 66.473,35.094 r0 bottom
CN12 "" CON_MOLEX_53047-0210 47.8,46.475 r180 bottom
D6 "DIODE_3P_DUAL_COMMON_CATHODE" DIO_SOT23 48.773,41.573 r90 bottom
D7 "BAT60JFILM" DIO_SOD323 79.125,61.563 r180 bottom
L1 "Inductor" IND_2016_MURATA_LQM2MPN2R2NG0 26.795,51.175 r180 top
L2 "Inductor" IND_2520_TOKO_DFE252012P 34.915,50.45 r0 top
L3 "Inductor" IND_2016_MURATA_LQM2MPN2R2NG0 21.85,49.075 r90 top
L4 "Inductor" IND_2520_TOKO_DFE252012P 36.425,44.6 r0 top
L5 "Inductor" IND_2016_MURATA_LQM2MPN2R2NG0 19.025,42.7 r180 top
L6 "Inductor" IND_2016_MURATA_LQM2MPN2R2NG0 35.5,40 r0 top
L7 "Inductor" IND_2016_MURATA_LQM2MPN2R2NG0 21.4,38.05 r180 top
LD11 "LED_green" LED_0603_OSRAM_LG-Q396-PS-35_GREEN_1A2K_H0P4 11.386,35.272 r270 top
LNK1 "link_200" LINK200 29.1,52.123 r0 top
LNK2 "link_200" LINK200 44.541,44.7 r90 top
LNK4 "link_200" LINK200 18.85,49.125 r180 top
LNK7 "link_200" LINK200 40.95,43.35 r270 top
LNK8 "link_200" LINK200 16.7,45.498 r0 top
LNK11 "link_200" LINK200 43.1,39.44 r180 top
R1 "Resistor" R0201_H0P23 66.751,43.42 r270 bottom
R2 "Resistor" R0201_H0P23 85.461,34.965 r90 bottom
R11 "Resistor" R0603 67,30.375 r90 bottom
R27 "Resistor" R0402 48.355,38.872 r180 top
R42 "Resistor" R0402 78.986,45.505 r270 bottom
R46 "" R0402 31.15,49.998 r270 top
R57 "" R0402 31.85,35.95 r90 top
R59 "" R0402 21.48,35.695 r90 top
R60 "" R0402 22.53,35.695 r90 top
R61 "" R0402 23.58,35.695 r90 top
R64 "" R0402 53.485,37.575 r180 top
R66 "Resistor" R0402 48.633,43.917 r180 bottom
R67 "Resistor" R0402 46.3,40.125 r270 bottom
R75 "" R0402 55.959,33.546 r0 top
R81 "" R0402 31.163,52.348 r270 top
R101 "Resistor" R0402 74.375,56.325 r90 bottom
R103 "Resistor" R0402 80.171,57.511 r90 bottom
R104 "Resistor" R0402 80.175,55.805 r270 bottom
R210 "Resistor" R0402 11.386,37.465 r270 top
R248 "Resistor" R0402 80.657,58.98 r0 bottom
R260 "Resistor" R0402 28.805,50.13 r270 bottom
R261 "Resistor" R0402 29.78,50.13 r270 bottom
R267 "" R0402 57.773,34.723 r180 bottom
R269 "" R0402 58.956,31.808 r90 top
R272 "Resistor" R0402 21.95,33.879 r0 bottom
R286 "" R0402 67.89,32.365 r90 bottom
TP21 "Test Point" TP_SMD_1MM 78.516,55.665 r90 bottom
U1 "STM32MP257FAK3" ICC_TFBGA424_14X14_P050_H1P20_CODE-B0A2 62.875,41.325 r0 top locked
U2 "MT53E1G32D2FW-046 WT:C" ICC_TFBGA200_10X14P5_P080_H1P05_PS0P3 85.26,41.29 r180 top locked
U26 "STPMIC25APQR" ICC_QFN56-EPAD_6P5X6P5_P040 28.5,43.8 r90 top
U37 "eMMC_THGBMTG5D1LBAIL" ICC_P-WFBGA153_13X11P5_P050 77.675,58.405 r0 top locked
X1 "XTAL_2_PINS" CRY_NX2012SA_2P 51.059,37.225 r270 top
X2 "XTAL_4_PINS" CRY_NX1612SA_4P 54.759,32.135 r180 top

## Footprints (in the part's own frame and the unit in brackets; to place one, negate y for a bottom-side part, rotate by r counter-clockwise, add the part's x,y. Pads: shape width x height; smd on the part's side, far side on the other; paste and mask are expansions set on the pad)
C0201_H0P5 [mm] "MCD-01534"
  rect 0.4x0.5 smd mask+0: 1(-0.3,0) 2(0.3,0)
C0201_MURATA_GRM033_H0P3 [mm] "GRM033R60J105ME11"
  rect 0.35x0.35 smd mask+0: 1(-0.275,0) 2(0.275,0)
C0402 [mm]
  rect 0.51x0.56 smd mask+0: 1(-0.45,0) 2(0.45,0)
C0603 [mm]
  rect 0.64x0.89 smd mask+0: 1(-0.7,0) 2(0.7,0)
  silkscreen extent -1.05,-0.55 1.02,0.55
C0805 [mm]
  rect 0.9x1.4 smd mask+0: 1(-0.85,0) 2(0.85,0)
  silkscreen extent -1.3,-0.77 1.3,0.77
CON_MOLEX_53047-0210 [mm]
  oval 1x1.3 hole 0.5 mask+0: 1(-0.625,0) 2(0.625,0)
  silkscreen extent -2.12,-1.15 2.13,2.05
CPOL_TCJ-B_1210_H210 [mm] "MCD-01791"
  rect 1.35x2.8 smd mask+0: 1(-1.375,0) 2(1.375,0)
  silkscreen extent -2.33,-1.68 1.85,1.68
CRY_NX1612SA_4P [mm] "MCD-02262"
  rect 0.75x0.6 smd mask+0: 1(-0.525,-0.375) 2(0.525,-0.375) 3(0.525,0.375) 4(-0.525,0.375)
  silkscreen extent -1.02,-0.8 0.03,0.6
CRY_NX2012SA_2P [mm]
  rect 1x1.25 smd mask+0: 1(-0.75,0) 2(0.75,0)
  silkscreen extent -1.05,-0.75 1.05,0.75
DIO_SOD323 [mm]
  rect 1.06x0.54 smd mask+0: 1(-1.07,0) 2(1.07,0)
  silkscreen extent -0.9,-0.72 0.9,0.72
DIO_SOT23 [mm]
  rect 1x1.4 smd mask+0: 1(-0.95,-1.1) 2(0.95,-1.1) 3(0,1.1)
  silkscreen extent -1.63,-0.82 1.63,0.82
ICC_P-WFBGA153_13X11P5_P050 [mm]
  round 0.23 smd mask+0: A1(-3.25,-3.25) A2(-3.25,-2.75) A3(-3.25,-2.25) A4(-3.25,-1.75) A5(-3.25,-1.25) A6(-3.25,-0.75) A7(-3.25,-0.25) A8(-3.25,0.25) A9(-3.25,0.75) A10(-3.25,1.25) A11(-3.25,1.75) A12(-3.25,2.25) A13(-3.25,2.75) A14(-3.25,3.25) B1(-2.75,-3.25) B2(-2.75,-2.75) B3(-2.75,-2.25) B4(-2.75,-1.75) B5(-2.75,-1.25) B6(-2.75,-0.75) B7(-2.75,-0.25) B8(-2.75,0.25) B9(-2.75,0.75) B10(-2.75,1.25) B11(-2.75,1.75) B12(-2.75,2.25) B13(-2.75,2.75) B14(-2.75,3.25) C1(-2.25,-3.25) C2(-2.25,-2.75) C3(-2.25,-2.25) C4(-2.25,-1.75) C5(-2.25,-1.25) C6(-2.25,-0.75) C7(-2.25,-0.25) C8(-2.25,0.25) C9(-2.25,0.75) C10(-2.25,1.25) C11(-2.25,1.75) C12(-2.25,2.25) C13(-2.25,2.75) C14(-2.25,3.25) D1(-1.75,-3.25) D2(-1.75,-2.75) D3(-1.75,-2.25) D4(-1.75,-1.75) D12(-1.75,2.25) D13(-1.75,2.75) D14(-1.75,3.25) E1(-1.25,-3.25) E2(-1.25,-2.75) E3(-1.25,-2.25) E5(-1.25,-1.25) E6(-1.25,-0.75) E7(-1.25,-0.25) E8(-1.25,0.25) E9(-1.25,0.75) E10(-1.25,1.25) E12(-1.25,2.25) E13(-1.25,2.75) E14(-1.25,3.25) F1(-0.75,-3.25) F2(-0.75,-2.75) F3(-0.75,-2.25) F5(-0.75,-1.25) F10(-0.75,1.25) F12(-0.75,2.25) F13(-0.75,2.75) F14(-0.75,3.25) G1(-0.25,-3.25) G2(-0.25,-2.75) G3(-0.25,-2.25) G5(-0.25,-1.25) G10(-0.25,1.25) G12(-0.25,2.25) G13(-0.25,2.75) G14(-0.25,3.25) H1(0.25,-3.25) H2(0.25,-2.75) H3(0.25,-2.25) H5(0.25,-1.25) H10(0.25,1.25) H12(0.25,2.25) H13(0.25,2.75) H14(0.25,3.25) J1(0.75,-3.25) J2(0.75,-2.75) J3(0.75,-2.25) J5(0.75,-1.25) J10(0.75,1.25) J12(0.75,2.25) J13(0.75,2.75) J14(0.75,3.25) K1(1.25,-3.25) K2(1.25,-2.75) K3(1.25,-2.25) K5(1.25,-1.25) K6(1.25,-0.75) K7(1.25,-0.25) K8(1.25,0.25) K9(1.25,0.75) K10(1.25,1.25) K12(1.25,2.25) K13(1.25,2.75) K14(1.25,3.25) L1(1.75,-3.25) L2(1.75,-2.75) L3(1.75,-2.25) L12(1.75,2.25) L13(1.75,2.75) L14(1.75,3.25) M1(2.25,-3.25) M2(2.25,-2.75) M3(2.25,-2.25) M4(2.25,-1.75) M5(2.25,-1.25) M6(2.25,-0.75) M7(2.25,-0.25) M8(2.25,0.25) M9(2.25,0.75) M10(2.25,1.25) M11(2.25,1.75) M12(2.25,2.25) M13(2.25,2.75) M14(2.25,3.25) N1(2.75,-3.25) N2(2.75,-2.75) N3(2.75,-2.25) N4(2.75,-1.75) N5(2.75,-1.25) N6(2.75,-0.75) N7(2.75,-0.25) N8(2.75,0.25) N9(2.75,0.75) N10(2.75,1.25) N11(2.75,1.75) N12(2.75,2.25) N13(2.75,2.75) N14(2.75,3.25) P1(3.25,-3.25) P2(3.25,-2.75) P3(3.25,-2.25) P4(3.25,-1.75) P5(3.25,-1.25) P6(3.25,-0.75) P7(3.25,-0.25) P8(3.25,0.25) P9(3.25,0.75) P10(3.25,1.25) P11(3.25,1.75) P12(3.25,2.25) P13(3.25,2.75) P14(3.25,3.25)
  silkscreen extent -6.78,-6.02 6.63,5.87
ICC_QFN56-EPAD_6P5X6P5_P040 [mm] "MCD-03000"
  rect 0.55x0.21 smd mask+0: 1(-3.245,2.6) 14(-3.245,-2.6) 29(3.245,-2.6) 42(3.245,2.6)
  rect 0.7x0.21 smd mask+0: 2(-3.17,2.2) 3(-3.17,1.8) 4(-3.17,1.4) 5(-3.17,1) 6(-3.17,0.6) 7(-3.17,0.2) 8(-3.17,-0.2) 9(-3.17,-0.6) 10(-3.17,-1) 11(-3.17,-1.4) 12(-3.17,-1.8) 13(-3.17,-2.2) 30(3.17,-2.2) 31(3.17,-1.8) 32(3.17,-1.4) 33(3.17,-1) 34(3.17,-0.6) 35(3.17,-0.2) 36(3.17,0.2) 37(3.17,0.6) 38(3.17,1) 39(3.17,1.4) 40(3.17,1.8) 41(3.17,2.2)
  rect 0.21x0.55 smd mask+0: 15(-2.6,-3.245) 28(2.6,-3.245) 43(2.6,3.245) 56(-2.6,3.245)
  rect 0.21x0.7 smd mask+0: 16(-2.2,-3.17) 17(-1.8,-3.17) 18(-1.4,-3.17) 19(-1,-3.17) 20(-0.6,-3.17) 21(-0.2,-3.17) 22(0.2,-3.17) 23(0.6,-3.17) 24(1,-3.17) 25(1.4,-3.17) 26(1.8,-3.17) 27(2.2,-3.17) 44(2.2,3.17) 45(1.8,3.17) 46(1.4,3.17) 47(1,3.17) 48(0.6,3.17) 49(0.2,3.17) 50(-0.2,3.17) 51(-0.6,3.17) 52(-1,3.17) 53(-1.4,3.17) 54(-1.8,3.17) 55(-2.2,3.17)
  rect 4.7x4.7 smd mask+0: 57(0,0)
  silkscreen extent -3.44,3 -3.01,3.42
ICC_TFBGA200_10X14P5_P080_H1P05_PS0P3 [mm] "MCD-04012"
  round 0.3 smd mask+0: A1(-4.4,6.825) A2(-3.6,6.825) A3(-2.8,6.825) A4(-2,6.825) A5(-1.2,6.825) A8(1.2,6.825) A9(2,6.825) A10(2.8,6.825) A11(3.6,6.825) A12(4.4,6.825) AA1(-4.4,-6.175) AA2(-3.6,-6.175) AA3(-2.8,-6.175) AA4(-2,-6.175) AA5(-1.2,-6.175) AA8(1.2,-6.175) AA9(2,-6.175) AA10(2.8,-6.175) AA11(3.6,-6.175) AA12(4.4,-6.175) AB1(-4.4,-6.825) AB2(-3.6,-6.825) AB3(-2.8,-6.825) AB4(-2,-6.825) AB5(-1.2,-6.825) AB8(1.2,-6.825) AB9(2,-6.825) AB10(2.8,-6.825) AB11(3.6,-6.825) AB12(4.4,-6.825) B1(-4.4,6.175) B2(-3.6,6.175) B3(-2.8,6.175) B4(-2,6.175) B5(-1.2,6.175) B8(1.2,6.175) B9(2,6.175) B10(2.8,6.175) B11(3.6,6.175) B12(4.4,6.175) C1(-4.4,5.525) C2(-3.6,5.525) C3(-2.8,5.525) C4(-2,5.525) C5(-1.2,5.525) C8(1.2,5.525) C9(2,5.525) C10(2.8,5.525) C11(3.6,5.525) C12(4.4,5.525) D1(-4.4,4.875) D2(-3.6,4.875) D3(-2.8,4.875) D4(-2,4.875) D5(-1.2,4.875) D8(1.2,4.875) D9(2,4.875) D10(2.8,4.875) D11(3.6,4.875) D12(4.4,4.875) E1(-4.4,4.225) E2(-3.6,4.225) E3(-2.8,4.225) E4(-2,4.225) E5(-1.2,4.225) E8(1.2,4.225) E9(2,4.225) E10(2.8,4.225) E11(3.6,4.225) E12(4.4,4.225) F1(-4.4,3.575) F2(-3.6,3.575) F3(-2.8,3.575) F4(-2,3.575) F5(-1.2,3.575) F8(1.2,3.575) F9(2,3.575) F10(2.8,3.575) F11(3.6,3.575) F12(4.4,3.575) G1(-4.4,2.925) G2(-3.6,2.925) G3(-2.8,2.925) G4(-2,2.925) G5(-1.2,2.925) G8(1.2,2.925) G9(2,2.925) G10(2.8,2.925) G11(3.6,2.925) G12(4.4,2.925) H1(-4.4,2.275) H2(-3.6,2.275) H3(-2.8,2.275) H4(-2,2.275) H5(-1.2,2.275) H8(1.2,2.275) H9(2,2.275) H10(2.8,2.275) H11(3.6,2.275) H12(4.4,2.275) J1(-4.4,1.625) J2(-3.6,1.625) J3(-2.8,1.625) J4(-2,1.625) J5(-1.2,1.625) J8(1.2,1.625) J9(2,1.625) J10(2.8,1.625) J11(3.6,1.625) J12(4.4,1.625) K1(-4.4,0.975) K2(-3.6,0.975) K3(-2.8,0.975) K4(-2,0.975) K5(-1.2,0.975) K8(1.2,0.975) K9(2,0.975) K10(2.8,0.975) K11(3.6,0.975) K12(4.4,0.975) N1(-4.4,-0.975) N2(-3.6,-0.975) N3(-2.8,-0.975) N4(-2,-0.975) N5(-1.2,-0.975) N8(1.2,-0.975) N9(2,-0.975) N10(2.8,-0.975) N11(3.6,-0.975) N12(4.4,-0.975) P1(-4.4,-1.625) P2(-3.6,-1.625) P3(-2.8,-1.625) P4(-2,-1.625) P5(-1.2,-1.625) P8(1.2,-1.625) P9(2,-1.625) P10(2.8,-1.625) P11(3.6,-1.625) P12(4.4,-1.625) R1(-4.4,-2.275) R2(-3.6,-2.275) R3(-2.8,-2.275) R4(-2,-2.275) R5(-1.2,-2.275) R8(1.2,-2.275) R9(2,-2.275) R10(2.8,-2.275) R11(3.6,-2.275) R12(4.4,-2.275) T1(-4.4,-2.925) T2(-3.6,-2.925) T3(-2.8,-2.925) T4(-2,-2.925) T5(-1.2,-2.925) T8(1.2,-2.925) T9(2,-2.925) T10(2.8,-2.925) T11(3.6,-2.925) T12(4.4,-2.925) U1(-4.4,-3.575) U2(-3.6,-3.575) U3(-2.8,-3.575) U4(-2,-3.575) U5(-1.2,-3.575) U8(1.2,-3.575) U9(2,-3.575) U10(2.8,-3.575) U11(3.6,-3.575) U12(4.4,-3.575) V1(-4.4,-4.225) V2(-3.6,-4.225) V3(-2.8,-4.225) V4(-2,-4.225) V5(-1.2,-4.225) V8(1.2,-4.225) V9(2,-4.225) V10(2.8,-4.225) V11(3.6,-4.225) V12(4.4,-4.225) W1(-4.4,-4.875) W2(-3.6,-4.875) W3(-2.8,-4.875) W4(-2,-4.875) W5(-1.2,-4.875) W8(1.2,-4.875) W9(2,-4.875) W10(2.8,-4.875) W11(3.6,-4.875) W12(4.4,-4.875) Y1(-4.4,-5.525) Y2(-3.6,-5.525) Y3(-2.8,-5.525) Y4(-2,-5.525) Y5(-1.2,-5.525) Y8(1.2,-5.525) Y9(2,-5.525) Y10(2.8,-5.525) Y11(3.6,-5.525) Y12(4.4,-5.525)
  silkscreen extent -5.2,-7.3 5.05,7.45
ICC_TFBGA424_14X14_P050_H1P20_CODE-B0A2 [mm] "MCD_03375"
  round 0.23 smd paste+0.025 mask+0: 1A1(-2.75,2.75) 1A3(-1.75,2.75) 1A5(-0.75,2.75) 1A7(0.25,2.75) 1A9(1.25,2.75) 1A11(2.25,2.75) 1B2(-2.25,2.25) 1B4(-1.25,2.25) 1B6(-0.25,2.25) 1B8(0.75,2.25) 1B10(1.75,2.25) 1B12(2.75,2.25) 1C1(-2.75,1.75) 1C3(-1.75,1.75) 1C5(-0.75,1.75) 1C7(0.25,1.75) 1C9(1.25,1.75) 1C11(2.25,1.75) 1D2(-2.25,1.25) 1D4(-1.25,1.25) 1D6(-0.25,1.25) 1D8(0.75,1.25) 1D10(1.75,1.25) 1D12(2.75,1.25) 1E1(-2.75,0.75) 1E3(-1.75,0.75) 1E5(-0.75,0.75) 1E7(0.25,0.75) 1E9(1.25,0.75) 1E11(2.25,0.75) 1F2(-2.25,0.25) 1F4(-1.25,0.25) 1F6(-0.25,0.25) 1F8(0.75,0.25) 1F10(1.75,0.25) 1F12(2.75,0.25) 1G1(-2.75,-0.25) 1G3(-1.75,-0.25) 1G5(-0.75,-0.25) 1G7(0.25,-0.25) 1G9(1.25,-0.25) 1G11(2.25,-0.25) 1H2(-2.25,-0.75) 1H4(-1.25,-0.75) 1H6(-0.25,-0.75) 1H8(0.75,-0.75) 1H10(1.75,-0.75) 1H12(2.75,-0.75) 1J1(-2.75,-1.25) 1J3(-1.75,-1.25) 1J5(-0.75,-1.25) 1J7(0.25,-1.25) 1J9(1.25,-1.25) 1J11(2.25,-1.25) 1K2(-2.25,-1.75) 1K4(-1.25,-1.75) 1K6(-0.25,-1.75) 1K8(0.75,-1.75) 1K10(1.75,-1.75) 1K12(2.75,-1.75) 1L1(-2.75,-2.25) 1L3(-1.75,-2.25) 1L5(-0.75,-2.25) 1L7(0.25,-2.25) 1L9(1.25,-2.25) 1L11(2.25,-2.25) 1M2(-2.25,-2.75) 1M4(-1.25,-2.75) 1M6(-0.25,-2.75) 1M8(0.75,-2.75) 1M10(1.75,-2.75) 1M12(2.75,-2.75) A1(-6.5,6.5) A2(-6,6.5) A3(-5.5,6.5) A6(-4,6.5) A7(-3.5,6.5) A10(-2,6.5) A11(-1.5,6.5) A14(0,6.5) A15(0.5,6.5) A18(2,6.5) A19(2.5,6.5) A22(4,6.5) A23(4.5,6.5) A26(6,6.5) A27(6.5,6.5) AA1(-6.5,-3.5) AA2(-6,-3.5) AA3(-5.5,-3.5) AA5(-4.5,-3.5) AA7(-3.5,-3.5) AA9(-2.5,-3.5) AA11(-1.5,-3.5) AA13(-0.5,-3.5) AA15(0.5,-3.5) AA17(1.5,-3.5) AA19(2.5,-3.5) AA21(3.5,-3.5) AA23(4.5,-3.5) AA25(5.5,-3.5) AA26(6,-3.5) AB1(-6.5,-4) AB2(-6,-4) AB3(-5.5,-4) AB4(-5,-4) AB6(-4,-4) AB8(-3,-4) AB10(-2,-4) AB12(-1,-4) AB14(0,-4) AB16(1,-4) AB18(2,-4) AB20(3,-4) AB22(4,-4) AB24(5,-4) AB25(5.5,-4) AB26(6,-4) AB27(6.5,-4) AC2(-6,-4.5) AC3(-5.5,-4.5) AC5(-4.5,-4.5) AC7(-3.5,-4.5) AC9(-2.5,-4.5) AC11(-1.5,-4.5) AC13(-0.5,-4.5) AC15(0.5,-4.5) AC17(1.5,-4.5) AC19(2.5,-4.5) AC21(3.5,-4.5) AC23(4.5,-4.5) AC25(5.5,-4.5) AC26(6,-4.5) AC27(6.5,-4.5) AD3(-5.5,-5) AD4(-5,-5) AD6(-4,-5) AD8(-3,-5) AD10(-2,-5) AD12(-1,-5) AD14(0,-5) AD16(1,-5) AD18(2,-5) AD20(3,-5) AD22(4,-5) AD24(5,-5) AD25(5.5,-5) AE1(-6.5,-5.5) AE2(-6,-5.5) AE3(-5.5,-5.5) AE4(-5,-5.5) AE5(-4.5,-5.5) AE6(-4,-5.5) AE7(-3.5,-5.5) AE8(-3,-5.5) AE9(-2.5,-5.5) AE10(-2,-5.5) AE11(-1.5,-5.5) AE12(-1,-5.5) AE13(-0.5,-5.5) AE14(0,-5.5) AE15(0.5,-5.5) AE16(1,-5.5) AE17(1.5,-5.5) AE18(2,-5.5) AE19(2.5,-5.5) AE20(3,-5.5) AE21(3.5,-5.5) AE22(4,-5.5) AE23(4.5,-5.5) AE24(5,-5.5) AE25(5.5,-5.5) AE26(6,-5.5) AF1(-6.5,-6) AF2(-6,-6) AF3(-5.5,-6) AF5(-4.5,-6) AF6(-4,-6) AF7(-3.5,-6) AF9(-2.5,-6) AF10(-2,-6) AF11(-1.5,-6) AF13(-0.5,-6) AF14(0,-6) AF15(0.5,-6) AF17(1.5,-6) AF18(2,-6) AF19(2.5,-6) AF21(3.5,-6) AF22(4,-6) AF23(4.5,-6) AF25(5.5,-6) AF26(6,-6) AF27(6.5,-6) AG1(-6.5,-6.5) AG2(-6,-6.5) AG5(-4.5,-6.5) AG6(-4,-6.5) AG9(-2.5,-6.5) AG10(-2,-6.5) AG13(-0.5,-6.5) AG14(0,-6.5) AG17(1.5,-6.5) AG18(2,-6.5) AG21(3.5,-6.5) AG22(4,-6.5) AG25(5.5,-6.5) AG26(6,-6.5) AG27(6.5,-6.5) B1(-6.5,6) B2(-6,6) B3(-5.5,6) B5(-4.5,6) B6(-4,6) B7(-3.5,6) B9(-2.5,6) B10(-2,6) B11(-1.5,6) B13(-0.5,6) B14(0,6) B15(0.5,6) B17(1.5,6) B18(2,6) B19(2.5,6) B21(3.5,6) B22(4,6) B23(4.5,6) B25(5.5,6) B26(6,6) B27(6.5,6) C2(-6,5.5) C3(-5.5,5.5) C4(-5,5.5) C5(-4.5,5.5) C6(-4,5.5) C7(-3.5,5.5) C8(-3,5.5) C9(-2.5,5.5) C10(-2,5.5) C11(-1.5,5.5) C12(-1,5.5) C13(-0.5,5.5) C14(0,5.5) C15(0.5,5.5) C16(1,5.5) C17(1.5,5.5) C18(2,5.5) C19(2.5,5.5) C20(3,5.5) C21(3.5,5.5) C22(4,5.5) C23(4.5,5.5) C24(5,5.5) C25(5.5,5.5) C26(6,5.5) C27(6.5,5.5) D3(-5.5,5) D4(-5,5) D6(-4,5) D8(-3,5) D10(-2,5) D12(-1,5) D14(0,5) D16(1,5) D18(2,5) D20(3,5) D22(4,5) D24(5,5) D25(5.5,5) E1(-6.5,4.5) E2(-6,4.5) E3(-5.5,4.5) E5(-4.5,4.5) E7(-3.5,4.5) E9(-2.5,4.5) E11(-1.5,4.5) E13(-0.5,4.5) E15(0.5,4.5) E17(1.5,4.5) E19(2.5,4.5) E21(3.5,4.5) E23(4.5,4.5) E25(5.5,4.5) E26(6,4.5) F1(-6.5,4) F2(-6,4) F3(-5.5,4) F4(-5,4) F6(-4,4) F8(-3,4) F10(-2,4) F12(-1,4) F14(0,4) F16(1,4) F18(2,4) F20(3,4) F22(4,4) F24(5,4) F25(5.5,4) F26(6,4) F27(6.5,4) G2(-6,3.5) G3(-5.5,3.5) G5(-4.5,3.5) G7(-3.5,3.5) G9(-2.5,3.5) G11(-1.5,3.5) G13(-0.5,3.5) G15(0.5,3.5) G17(1.5,3.5) G19(2.5,3.5) G21(3.5,3.5) G23(4.5,3.5) G25(5.5,3.5) G26(6,3.5) G27(6.5,3.5) H3(-5.5,3) H4(-5,3) H6(-4,3) H22(4,3) H24(5,3) H25(5.5,3) J1(-6.5,2.5) J2(-6,2.5) J3(-5.5,2.5) J5(-4.5,2.5) J7(-3.5,2.5) J21(3.5,2.5) J23(4.5,2.5) J25(5.5,2.5) J26(6,2.5) K1(-6.5,2) K2(-6,2) K3(-5.5,2) K4(-5,2) K6(-4,2) K22(4,2) K24(5,2) K25(5.5,2) K26(6,2) K27(6.5,2) L2(-6,1.5) L3(-5.5,1.5) L5(-4.5,1.5) L7(-3.5,1.5) L21(3.5,1.5) L23(4.5,1.5) L25(5.5,1.5) L26(6,1.5) L27(6.5,1.5) M3(-5.5,1) M4(-5,1) M6(-4,1) M22(4,1) M24(5,1) M25(5.5,1) N1(-6.5,0.5) N2(-6,0.5) N3(-5.5,0.5) N5(-4.5,0.5) N7(-3.5,0.5) N21(3.5,0.5) N23(4.5,0.5) N25(5.5,0.5) N26(6,0.5) P1(-6.5,0) P2(-6,0) P3(-5.5,0) P4(-5,0) P6(-4,0) P22(4,0) P24(5,0) P25(5.5,0) P26(6,0) P27(6.5,0) R2(-6,-0.5) R3(-5.5,-0.5) R5(-4.5,-0.5) R7(-3.5,-0.5) R21(3.5,-0.5) R23(4.5,-0.5) R25(5.5,-0.5) R26(6,-0.5) R27(6.5,-0.5) T3(-5.5,-1) T4(-5,-1) T6(-4,-1) T22(4,-1) T24(5,-1) T25(5.5,-1) U1(-6.5,-1.5) U2(-6,-1.5) U3(-5.5,-1.5) U5(-4.5,-1.5) U7(-3.5,-1.5) U21(3.5,-1.5) U23(4.5,-1.5) U25(5.5,-1.5) U26(6,-1.5) V1(-6.5,-2) V2(-6,-2) V3(-5.5,-2) V4(-5,-2) V6(-4,-2) V22(4,-2) V24(5,-2) V25(5.5,-2) V26(6,-2) V27(6.5,-2) W2(-6,-2.5) W3(-5.5,-2.5) W5(-4.5,-2.5) W7(-3.5,-2.5) W21(3.5,-2.5) W23(4.5,-2.5) W25(5.5,-2.5) W26(6,-2.5) W27(6.5,-2.5) Y3(-5.5,-3) Y4(-5,-3) Y6(-4,-3) Y22(4,-3) Y24(5,-3) Y25(5.5,-3)
  silkscreen extent -7.17,-7 7,7.17
IND_2016_MURATA_LQM2MPN2R2NG0 [mm]
  rect 0.8x1.8 smd mask+0: 1(-0.8,0) 2(0.8,0)
  silkscreen extent -0.28,-0.87 0.28,0.87
IND_2520_TOKO_DFE252012P [mm]
  rect 0.8x2 smd mask+0: 1(-1,0) 2(1,0)
  silkscreen extent -1.35,-1.12 1.35,1.12
LED_0603_OSRAM_LG-Q396-PS-35_GREEN_1A2K_H0P4 [mm]
  rect 0.8x0.8 smd mask+0: 1(-0.75,0) 2(0.75,0)
  silkscreen extent -0.85,-0.53 1.28,0.53
LINK200 [mm]
  rect 0.2x0.35 smd paste-10 mask+0: 1(0,-0.225) 2(0,0.225)
R0201_H0P23 [mm] "MCD-00702"
  rect 0.4x0.5 smd mask+0: 1(-0.3,0) 2(0.3,0)
R0402 [mm]
  rect 0.51x0.7 smd mask+0: 1(-0.45,0) 2(0.45,0)
R0603 [mm]
  rect 0.64x1 smd mask+0: 1(-0.7,0) 2(0.7,0)
  silkscreen extent -1.05,-0.58 1.05,0.58
SWI_WE_434121025816 [mm] "MCD-03492"
  rect 1.5x1.4 smd: 1(-3.25,0) 2(3.25,0)
  silkscreen extent -3,-1.95 3,1.95
TP_SMD_1MM [mm]
  round 1 smd paste-10 mask+0: 1(0,0)
  silkscreen extent -0.7,-0.7 0.7,0.7

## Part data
B2: library part MCD-03492, "Switch tactile, SPST-NO, 50mA, 12V, 6x3.8mm"
C2 C3 C10 C11: library part MCD-01341, "Capacitor, MLCC, 10uF, 6V3, X5R, 20%, 0603, T=0,8mm"
C4 C5 C6 C7 C8 C9 C12 C13 C14 C15 C16 C17 C18 C19 C20 C21 C118 C130: library part MCD-00006, "Capacitor, MLCC, 100nF, 16V, X7R, +/-10%, 0402, T=0.5mm"
C22 C23 C24 C26 C27 C28 C34 C35 C36 C37 C41 C183 C200 C202: library part MCD-00100, "Capacitor, MLCC, 22uF, 6V3, X5R, +/-20%, 0603, T=0,8mm"
C29 C30 C32 C38 C56 C184 C199: library part MCD-00099, "Capacitor, MLCC, 10uF, 10V, X5R, +/-10%, 0603, T=0,8mm"
C33: library part MCD-00011, "Capacitor, MLCC, 10nF, 16V, X7R, 10%, 0402, T=0.5mm"
C39 C43 C188 C213 C216: library part MCD-00095, "Capacitor, MLCC, 1uF, 25V, X5R, +/-10%, 0402, T=0.5mm"
C40: library part MCD-03140, "Capacitor, MLCC, 10uF, 6.3V, X5R, +/-20%, 0402, T=0.5mm"
C42 C147: library part MCD-01796, "Capacitor, Tantalum, 100uF, 6V3, 40mR, +/-20%,  Type_B (3528 metric), T=1.9mm"
C44 C45 C46 C47 C48 C49 C50 C51 C52 C53 C54 C55 C57 C58 C59 C60 C62 C63 C64 C65 C66 C67 C68 C69 C70 C71 C72 C73 C74 C75 C76 C77 C82 C83 C151 C250 C252 C260: library part MCD-02377, "Capacitor, MLCC, 1uF, 6.3V, X5R, +/-20%, 0201, T=0,3mm"
C61 C91 C189 C190 C208 C209 C214 C215 C217: library part MCD-01356, "Capacitor, MLCC, 4.7uF, 6V3, X5R, +/-20%, 0402, T=0.5mm"
C81 C86 C90 C92: library part MCD-00674, "Capacitor, MLCC, 6.8pF, 50V, NPO, +-0.25pF, 0402, T=0.5mm"
C87: library part MCD-00006, "Capacitor,100nF,16V,X7R,10%,0402"
C88: library part MCD-01823, "Capacitor, MLCC, 2.2uF, 6V3, X5R,+/-10%, 0402, T=0.5mm"
C117 C128 C148: library part MCD-02606, "Capacitor, MLCC, 2.2uF, 6.3V, X5R, +/-10%, 0402, T=0.5mm"
C185 C186 C187 C193 C194 C198 C203 C204 C206 C207: library part MCD-03139, "Capacitor, MLCC, 22uF, 10V, X5R, +/-20%, 0805, T=1,25mm"
C192 C195 C196 C197 C201 C205 C220 C234 C236 C237 C238 C239 C240 C244 C246 C248 C251 C253: library part MCD-01535, "Capacitor, MLCC,100nF, 10V, X7R, +/-10%, 0201, T=0.3mm"
C219: library part MCD-02198, "Capacitor, MLCC, 10nF, 50V, X7R, +/-10%, 0402, T=0.5mm"
C225: library part MCD-01534, "Capacitor, MLCC, 4,7uF, 6V3, X5R, +/-20%, 0201, T=0.5mm"
C235: library part MCD-02235, "Capacitor, MLCC, 2.2uF, 10V, X5R,+/-10%, 0201, T=0.5mm"
CN12: library part MCD-00655, "Header 2 circuits, 1.25mm Pitch ,  Vertical, with Friction Lock"
D6: library part MCD-03280, "Diode, Schottky, Dual Common Cathode, 0V3, 300mA, 40V, SOT-23"
D7: library part MCD-00034
L1 L6: library part MCD-03143, "Inductor, 2.2uH, +/-20%, Itemp= 1700mA, Isat= 2400mA, 0R140, 0806, T=1mm"
L2 L4: library part MCD-03142, "Inductor, 0.68uH, +/-20%, Itemp= 3900mA, Isat= 5400mA, 0R031, 1008, T=1.2mm"
L3 L5 L7: library part MCD-03141, "Inductor, 0.68uH, +/-20%, Itemp= 3100mA, Isat= 4300mA, 0R043, 0806, T=1mm"
LD11: library part MCD-00588, "LED Green, 0603 SMD, Forward Voltage Typ=2V, Max=2.5V"
LNK1 LNK2 LNK4 LNK7 LNK8 LNK11: library part MCD-02777, "Track link on PCB 200um width for layout routing"
R1 R2: library part MCD-02253, "Resistor, 240R, 0201, +/-1%, 1/20W"
R11: library part MCD-00056, "Resistor, 0R, 0603, +/-5%, 1/10W"
R27 R101 R103 R104 R248 R272: library part MCD-00053, "Resistor,10K,0402,1%,1/16W"
R42: library part MCD-00053, "Resistor, 10K, 0402, +/-1%, 1/16W"
R46 R57 R59 R60 R61 R64 R75 R81 R267 R269 R286: library part MCD-00052, "Resistor,0R,0402,5%,1/16W"
R66: library part MCD-00058, "Resistor, 20R, 0402, +/-1%, 1/16W"
R67: library part MCD-00052, "Resistor, 0R, 0402, +/-5%, 1/16W"
R210: library part MCD-00441, "Resistor,270R,0402,1%,1/16W"
R260 R261: library part MCD-00068, "Resistor,1K5,0402,1%,1/16W"
TP21: library part MCD-00074, "Test Point 1mm"
U1: library part MCD-03375, "MPU , 2xCortex-A35@1.5GHz, Cortex-M33@400MHz, TFBGA 14x14, pitch 0.5, 808 KB SRAM, With Crypto"
U2: library part MCD-04160, "Memory, LPDDR4 SDRAM,1V8, 32Gbit, 2133MHz"
U26: library part MCD-03000, "STPMIC2"
U37: library part MCD-02799, "Memory, eMMC, 4GB, 15nm ,WFBGA , 153 pins"
X1: library part MCD-01479, "Crystal, 32.768kHz, 6pF, +/-20ppm, 80K, 2.05x1.2mm"
X2: library part MCD-02344, "Crystal, 40MHz, 6pF, +/-20ppm, 80R, 1.6x1.2mm"

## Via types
v1: diameter 0.55, hole 0.35, Top Layer to Bottom Layer, 277 vias
v2: diameter 0.4, hole 0.2, Top Layer to Bottom Layer, tented both sides, 229 vias
v3: diameter 0.5, hole 0.2, Top Layer to Bottom Layer, 146 vias
v4: diameter 0.4, hole 0.2, Top Layer to Bottom Layer, 105 vias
